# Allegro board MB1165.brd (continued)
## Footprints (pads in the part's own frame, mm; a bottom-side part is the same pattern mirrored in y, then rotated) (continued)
BNX001
  round 1.981 hole 1.219: 1(2.5,2.5) 2(-2.5,2.5) 3(2.5,-2.5) 4(0,0) 5(5,0) 6(-2.5,-2.5)
C310M-6
  rect 5.08x3.048 smd: 1(3.175,0) 2(-3.175,0)
CAE_5R3X5R3_H5R4
  rect 2.718x1.168 smd: 1(-2.05,0) 2(2.05,0)
CLM-120-02-L-D
  rect 0.61x1.499 smd: 1(-9.5,-1.57) 2(-9.5,1.57) 3(-8.5,-1.57) 4(-8.5,1.57) 5(-7.5,-1.57) 6(-7.5,1.57) 7(-6.5,-1.57) 8(-6.5,1.57) 9(-5.5,-1.57) 10(-5.5,1.57) 11(-4.5,-1.57) 12(-4.5,1.57) 13(-3.5,-1.57) 14(-3.5,1.57) 15(-2.5,-1.57) 16(-2.5,1.57) 17(-1.5,-1.57) 18(-1.5,1.57) 19(-0.5,-1.57) 20(-0.5,1.57) 21(0.5,-1.57) 22(0.5,1.57) 23(1.5,-1.57) 24(1.5,1.57) 25(2.5,-1.57) 26(2.5,1.57) 27(3.5,-1.57) 28(3.5,1.57) 29(4.5,-1.57) 30(4.5,1.57) 31(5.5,-1.57) 32(5.5,1.57) 33(6.5,-1.57) 34(6.5,1.57) 35(7.5,-1.57) 36(7.5,1.57) 37(8.5,-1.57) 38(8.5,1.57) 39(9.5,-1.57) 40(9.5,1.57)
  round 4.699 hole 3.2: 41(-15.249,0) 42(15.25,0)
COUPON
  rect 1.422x1.422 hole 1.016: 1(-3.444,-2.54)
  round 1.422 hole 1.016: 2(-3.444,0) 3(-3.444,2.54) 4(3.447,-2.54) 5(3.447,0) 6(3.447,2.54)
DB9_M
  rect 1.778x2.032 hole 0.965: 1(5.537,0)
  oval 1.778x2.032 hole 0.965: 2(2.769,0) 3(0,0) 4(-2.769,0) 5(-5.537,0) 6(4.166,2.794) 7(1.397,2.794) 8(-1.372,2.794) 9(-4.14,2.794)
  oval 4.572x2.286 hole 3.556x1.27: 10(-12.522,1.397) 11(12.522,1.397)
FBGA64_1_11X13
  round 0.457 smd: A1(-3.5,3.5) A2(-2.5,3.5) A3(-1.5,3.5) A4(-0.5,3.5) A5(0.5,3.5) A6(1.5,3.5) A7(2.5,3.5) A8(3.5,3.5) B1(-3.5,2.5) B2(-2.5,2.5) B3(-1.5,2.5) B4(-0.5,2.5) B5(0.5,2.5) B6(1.5,2.5) B7(2.5,2.5) B8(3.5,2.5) C1(-3.5,1.5) C2(-2.5,1.5) C3(-1.5,1.5) C4(-0.5,1.5) C5(0.5,1.5) C6(1.5,1.5) C7(2.5,1.5) C8(3.5,1.5) D1(-3.5,0.5) D2(-2.5,0.5) D3(-1.5,0.5) D4(-0.5,0.5) D5(0.5,0.5) D6(1.5,0.5) D7(2.5,0.5) D8(3.5,0.5) E1(-3.5,-0.5) E2(-2.5,-0.5) E3(-1.5,-0.5) E4(-0.5,-0.5) E5(0.5,-0.5) E6(1.5,-0.5) E7(2.5,-0.5) E8(3.5,-0.5) F1(-3.5,-1.5) F2(-2.5,-1.5) F3(-1.5,-1.5) F4(-0.5,-1.5) F5(0.5,-1.5) F6(1.5,-1.5) F7(2.5,-1.5) F8(3.5,-1.5) G1(-3.5,-2.5) G2(-2.5,-2.5) G3(-1.5,-2.5) G4(-0.5,-2.5) G5(0.5,-2.5) G6(1.5,-2.5) G7(2.5,-2.5) G8(3.5,-2.5) H1(-3.5,-3.5) H2(-2.5,-3.5) H3(-1.5,-3.5) H4(-0.5,-3.5) H5(0.5,-3.5) H6(1.5,-3.5) H7(2.5,-3.5) H8(3.5,-3.5)
FBGA90_0R8_8X13
  round 0.406 smd: A1(-3.2,5.6) A2(-2.4,5.6) A3(-1.6,5.6) A7(1.6,5.6) A8(2.4,5.6) A9(3.2,5.6) B1(-3.2,4.8) B2(-2.4,4.8) B3(-1.6,4.8) B7(1.6,4.8) B8(2.4,4.8) B9(3.2,4.8) C1(-3.2,4) C2(-2.4,4) C3(-1.6,4) C7(1.6,4) C8(2.4,4) C9(3.2,4) D1(-3.2,3.2) D2(-2.4,3.2) D3(-1.6,3.2) D7(1.6,3.2) D8(2.4,3.2) D9(3.2,3.2) E1(-3.2,2.4) E2(-2.4,2.4) E3(-1.6,2.4) E7(1.6,2.4) E8(2.4,2.4) E9(3.2,2.4) F1(-3.2,1.6) F2(-2.4,1.6) F3(-1.6,1.6) F7(1.6,1.6) F8(2.4,1.6) F9(3.2,1.6) G1(-3.2,0.8) G2(-2.4,0.8) G3(-1.6,0.8) G7(1.6,0.8) G8(2.4,0.8) G9(3.2,0.8) H1(-3.2,0) H2(-2.4,0) H3(-1.6,0) H7(1.6,0) H8(2.4,0) H9(3.2,0) J1(-3.2,-0.8) J2(-2.4,-0.8) J3(-1.6,-0.8) J7(1.6,-0.8) J8(2.4,-0.8) J9(3.2,-0.8) K1(-3.2,-1.6) K2(-2.4,-1.6) K3(-1.6,-1.6) K7(1.6,-1.6) K8(2.4,-1.6) K9(3.2,-1.6) L1(-3.2,-2.4) L2(-2.4,-2.4) L3(-1.6,-2.4) L7(1.6,-2.4) L8(2.4,-2.4) L9(3.2,-2.4) M1(-3.2,-3.2) M2(-2.4,-3.2) M3(-1.6,-3.2) M7(1.6,-3.2) M8(2.4,-3.2) M9(3.2,-3.2) N1(-3.2,-4) N2(-2.4,-4) N3(-1.6,-4) N7(1.6,-4) N8(2.4,-4) N9(3.2,-4) P1(-3.2,-4.8) P2(-2.4,-4.8) P3(-1.6,-4.8) P7(1.6,-4.8) P8(2.4,-4.8) P9(3.2,-4.8) R1(-3.2,-5.6) R2(-2.4,-5.6) R3(-1.6,-5.6) R7(1.6,-5.6) R8(2.4,-5.6) R9(3.2,-5.6)
FTR-120-53-L-D-LC
  round 1.194 hole 1.194 unplated: (-11.43,0) (11.43,0)
  rect 0.711x2.896 smd: 1(-12.065,-2.705) 2(-12.065,2.705) 3(-10.795,-2.705) 4(-10.795,2.705) 5(-9.525,-2.705) 6(-9.525,2.705) 7(-8.255,-2.705) 8(-8.255,2.705) 9(-6.985,-2.705) 10(-6.985,2.705) 11(-5.715,-2.705) 12(-5.715,2.705) 13(-4.445,-2.705) 14(-4.445,2.705) 15(-3.175,-2.705) 16(-3.175,2.705) 17(-1.905,-2.705) 18(-1.905,2.705) 19(-0.635,-2.705) 20(-0.635,2.705) 21(0.635,-2.705) 22(0.635,2.705) 23(1.905,-2.705) 24(1.905,2.705) 25(3.175,-2.705) 26(3.175,2.705) 27(4.445,-2.705) 28(4.445,2.705) 29(5.715,-2.705) 30(5.715,2.705) 31(6.985,-2.705) 32(6.985,2.705) 33(8.255,-2.705) 34(8.255,2.705) 35(9.525,-2.705) 36(9.525,2.705) 37(10.795,-2.705) 38(10.795,2.705) 39(12.065,-2.705) 40(12.065,2.705)
FTR-130-53-L-D-LC
  round 1.194 hole 1.194 unplated: (-17.78,0) (17.78,0)
  rect 0.711x2.896 smd: 1(-18.415,-2.705) 2(-18.415,2.705) 3(-17.145,-2.705) 4(-17.145,2.705) 5(-15.875,-2.705) 6(-15.875,2.705) 7(-14.605,-2.705) 8(-14.605,2.705) 9(-13.335,-2.705) 10(-13.335,2.705) 11(-12.065,-2.705) 12(-12.065,2.705) 13(-10.795,-2.705) 14(-10.795,2.705) 15(-9.525,-2.705) 16(-9.525,2.705) 17(-8.255,-2.705) 18(-8.255,2.705) 19(-6.985,-2.705) 20(-6.985,2.705) 21(-5.715,-2.705) 22(-5.715,2.705) 23(-4.445,-2.705) 24(-4.445,2.705) 25(-3.175,-2.705) 26(-3.175,2.705) 27(-1.905,-2.705) 28(-1.905,2.705) 29(-0.635,-2.705) 30(-0.635,2.705) 31(0.635,-2.705) 32(0.635,2.705) 33(1.905,-2.705) 34(1.905,2.705) 35(3.175,-2.705) 36(3.175,2.705) 37(4.445,-2.705) 38(4.445,2.705) 39(5.715,-2.705) 40(5.715,2.705) 41(6.985,-2.705) 42(6.985,2.705) 43(8.255,-2.705) 44(8.255,2.705) 45(9.525,-2.705) 46(9.525,2.705) 47(10.795,-2.705) 48(10.795,2.705) 49(12.065,-2.705) 50(12.065,2.705) 51(13.335,-2.705) 52(13.335,2.705) 53(14.605,-2.705) 54(14.605,2.705) 55(15.875,-2.705) 56(15.875,2.705) 57(17.145,-2.705) 58(17.145,2.705) 59(18.415,-2.705) 60(18.415,2.705)
FTSH-110-01-L-DV
  round 0.965 hole 0.965 unplated: (-5.08,0) (5.08,0)
  rect 0.737x2.794 smd: 1(-5.715,-2.03) 2(-5.715,2.03) 3(-4.445,-2.03) 4(-4.445,2.03) 5(-3.175,-2.03) 6(-3.175,2.03) 7(-1.905,-2.03) 8(-1.905,2.03) 9(-0.635,-2.03) 10(-0.635,2.03) 11(0.635,-2.03) 12(0.635,2.03) 13(1.905,-2.03) 14(1.905,2.03) 15(3.175,-2.03) 16(3.175,2.03) 17(4.445,-2.03) 18(4.445,2.03) 19(5.715,-2.03) 20(5.715,2.03)
FTSH-125-01-F-DV
  round 0.965 hole 0.965 unplated: (-14.605,0) (14.605,0)
  rect 0.737x2.794 smd: 1(-15.24,-2.03) 2(-15.24,2.03) 3(-13.97,-2.03) 4(-13.97,2.03) 5(-12.7,-2.03) 6(-12.7,2.03) 7(-11.43,-2.03) 8(-11.43,2.03) 9(-10.16,-2.03) 10(-10.16,2.03) 11(-8.89,-2.03) 12(-8.89,2.03) 13(-7.62,-2.03) 14(-7.62,2.03) 15(-6.35,-2.03) 16(-6.35,2.03) 17(-5.08,-2.03) 18(-5.08,2.03) 19(-3.81,-2.03) 20(-3.81,2.03) 21(-2.54,-2.03) 22(-2.54,2.03) 23(-1.27,-2.03) 24(-1.27,2.03) 25(0,-2.03) 26(0,2.03) 27(1.27,-2.03) 28(1.27,2.03) 29(2.54,-2.03) 30(2.54,2.03) 31(3.81,-2.03) 32(3.81,2.03) 33(5.08,-2.03) 34(5.08,2.03) 35(6.35,-2.03) 36(6.35,2.03) 37(7.62,-2.03) 38(7.62,2.03) 39(8.89,-2.03) 40(8.89,2.03) 41(10.16,-2.03) 42(10.16,2.03) 43(11.43,-2.03) 44(11.43,2.03) 45(12.7,-2.03) 46(12.7,2.03) 47(13.97,-2.03) 48(13.97,2.03) 49(15.24,-2.03) 50(15.24,2.03)
HDR_2X3-1_2R54-6
  rect 1.524x1.524 hole 1.016: 1(0,0)
  round 1.524 hole 1.016: 2(0,2.54) 3(2.54,0) 4(2.54,2.54) 5(5.08,0)
HDR_2X6_2R54
  rect 1.524x1.524 hole 1.016: 1(0,0)
  round 1.524 hole 1.016: 2(0,2.54) 3(2.54,0) 4(2.54,2.54) 5(5.08,0) 6(5.08,2.54) 7(7.62,0) 8(7.62,2.54) 9(10.16,0) 10(10.16,2.54) 11(12.7,0) 12(12.7,2.54)
HOLE_C9D4R5
  round 8.992 hole 4.496: 1(0,0)
IDC20S
  round 1.524 hole 1.016: 1(0,0) 2(2.54,0) 3(0,-2.54) 4(2.54,-2.54) 5(0,-5.08) 6(2.54,-5.08) 7(0,-7.62) 8(2.54,-7.62) 9(0,-10.16) 10(2.54,-10.16) 11(0,-12.7) 12(2.54,-12.7) 13(0,-15.24) 14(2.54,-15.24) 15(0,-17.78) 16(2.54,-17.78) 17(0,-20.32) 18(2.54,-20.32) 19(0,-22.86) 20(2.54,-22.86)
IDC34S
  rect 1.524x1.524 hole 1.016: 1(0,0)
  round 1.524 hole 1.016: 2(2.54,0) 3(0,-2.54) 4(2.54,-2.54) 5(0,-5.08) 6(2.54,-5.08) 7(0,-7.62) 8(2.54,-7.62) 9(0,-10.16) 10(2.54,-10.16) 11(0,-12.7) 12(2.54,-12.7) 13(0,-15.24) 14(2.54,-15.24) 15(0,-17.78) 16(2.54,-17.78) 17(0,-20.32) 18(2.54,-20.32) 19(0,-22.86) 20(2.54,-22.86) 21(0,-25.4) 22(2.54,-25.4) 23(0,-27.94) 24(2.54,-27.94) 25(0,-30.48) 26(2.54,-30.48) 27(0,-33.02) 28(2.54,-33.02) 29(0,-35.56) 30(2.54,-35.56) 31(0,-38.1) 32(2.54,-38.1) 33(0,-40.64) 34(2.54,-40.64)
IR_VISHAY3
  rect 0.711x1.397 smd: 1(3.325,0) 2(2.375,0) 3(1.425,0) 4(0.475,0) 5(-0.475,0) 6(-1.425,0) 7(-2.375,0) 8(-3.325,0)
LED2_3528
  rect 1.118x1.499 smd: 1(-0.75,-1.5) 2(-0.75,1.5) 3(0.75,1.5) 4(0.75,-1.5)
LQFP48_0R5_9X9
  rect 1.346x0.279 smd: 1(-4.35,2.75) 2(-4.35,2.25) 3(-4.35,1.75) 4(-4.35,1.25) 5(-4.35,0.75) 6(-4.35,0.25) 7(-4.35,-0.25) 8(-4.35,-0.75) 9(-4.35,-1.25) 10(-4.35,-1.75) 11(-4.35,-2.25) 12(-4.35,-2.75) 25(4.35,-2.75) 26(4.35,-2.25) 27(4.35,-1.75) 28(4.35,-1.25) 29(4.35,-0.75) 30(4.35,-0.25) 31(4.35,0.25) 32(4.35,0.75) 33(4.35,1.25) 34(4.35,1.75) 35(4.35,2.25) 36(4.35,2.75)
  rect 0.279x1.346 smd: 13(-2.75,-4.35) 14(-2.25,-4.35) 15(-1.75,-4.35) 16(-1.25,-4.35) 17(-0.75,-4.35) 18(-0.25,-4.35) 19(0.25,-4.35) 20(0.75,-4.35) 21(1.25,-4.35) 22(1.75,-4.35) 23(2.25,-4.35) 24(2.75,-4.35) 37(2.75,4.35) 38(2.25,4.35) 39(1.75,4.35) 40(1.25,4.35) 41(0.75,4.35) 42(0.25,4.35) 43(-0.25,4.35) 44(-0.75,4.35) 45(-1.25,4.35) 46(-1.75,4.35) 47(-2.25,4.35) 48(-2.75,4.35)
MOLEX_47590001
  rect 0.406x1.346 smd: 1(1.3,0) 2(0.65,0) 3(0,0) 4(-0.65,0) 5(-1.3,0)
  oval 1.067x1.6 hole 0.762x0.838: 6(2.275,0.325) 7(-2.275,0.325)
  oval 1.397x1.905 hole 0.838x1.499: 8(-4.15,-2.855) 9(4.15,-2.855)
  rect 2.896x2.007 smd: 10(0,-2.675)
MP34DT01TR
  rect 0.508x1.067 smd: 1(-0.425,0.675) 2(-0.425,-0.675) 3(0.425,-0.675) 4(0.425,0.675)
  round 0.152 smd: 5(-0.025,-1.753)
MSD_PJS008_
  round 0.711 hole 0.711 unplated: (0,0) (7.55,0)
  rect 0.813x1.6 smd: 1(1.475,5.8) 2(2.575,5.8) 3(3.675,5.8) 4(4.775,5.8) 5(5.875,5.8) 6(6.975,5.8) 7(8.075,5.8) 8(9.175,5.8)
  rect 0.838x1.6 smd: 9(10.325,5.8)
  rect 1.956x1.905 smd: 10(11.225,-4.4)
  rect 1.524x3.073 smd: 11(11.45,-7.35)
  rect 1.397x3.429 smd: 12(-3.503,-7.357)
  rect 1.6x3.505 smd: 13(-3.4,3.65)
  rect 1.194x3.099 smd: 14(11.6,4.15)
OSC_4SM_7X5
  rect 1.803x2.007 smd: 1(-2.54,-2.1) 2(2.54,-2.1) 3(2.54,2.1) 4(-2.54,2.1)
PB10
  rect 1.524x1.016 smd: 1(-4.5,-2.223) 2(-4.5,2.223) 3(4.5,2.223) 4(4.5,-2.223)
PJ3028B
  round 2.007 hole 2.007 unplated: (0,0) (7,0)
  rect 1.219x2.489 smd: 2(-3.9,-4) 7(-2,4)
  rect 2.007x2.489 smd: 3(-1,-4) 4(0.8,4) 6(8.2,-4)
  rect 2.489x2.007 smd: 5(12.25,0.8)
PWR_JACK_DC10
  rect 2.032x4.216 hole 1.016x3.2: 1(0,0)
  oval 4.216x2.032 hole 3.2x1.016: 2(-3.1,-5)
  oval 2.032x4.216 hole 1.016x3.2: 3(-6.2,0)
QFN32_0R5_5X5
  oval 0.864x0.279 smd: 1(-2.42,1.75) 2(-2.42,1.25) 3(-2.42,0.75) 4(-2.42,0.25) 5(-2.42,-0.25) 6(-2.42,-0.75) 7(-2.42,-1.25) 8(-2.42,-1.75) 17(2.42,-1.75) 18(2.42,-1.25) 19(2.42,-0.75) 20(2.42,-0.25) 21(2.42,0.25) 22(2.42,0.75) 23(2.42,1.25) 24(2.42,1.75)
  oval 0.279x0.864 smd: 9(-1.75,-2.42) 10(-1.25,-2.42) 11(-0.75,-2.42) 12(-0.25,-2.42) 13(0.25,-2.42) 14(0.75,-2.42) 15(1.25,-2.42) 16(1.75,-2.42) 25(1.75,2.42) 26(1.25,2.42) 27(0.75,2.42) 28(0.25,2.42) 29(-0.25,2.42) 30(-0.75,2.42) 31(-1.25,2.42) 32(-1.75,2.42)
  rect 3.429x3.429 smd: 33(0,0)
QSH-030-01-F-D-A
  round 1.016 hole 1.016 unplated: (-10.065,2.67) (10.065,2.67)
  rect 0.279x2.286 smd: 1(-7.25,-2.87) 2(-7.25,2.87) 3(-6.75,-2.87) 4(-6.75,2.87) 5(-6.25,-2.87) 6(-6.25,2.87) 7(-5.75,-2.87) 8(-5.75,2.87) 9(-5.25,-2.87) 10(-5.25,2.87) 11(-4.75,-2.87) 12(-4.75,2.87) 13(-4.25,-2.87) 14(-4.25,2.87) 15(-3.75,-2.87) 16(-3.75,2.87) 17(-3.25,-2.87) 18(-3.25,2.87) 19(-2.75,-2.87) 20(-2.75,2.87) 21(-2.25,-2.87) 22(-2.25,2.87) 23(-1.75,-2.87) 24(-1.75,2.87) 25(-1.25,-2.87) 26(-1.25,2.87) 27(-0.75,-2.87) 28(-0.75,2.87) 29(-0.25,-2.87) 30(-0.25,2.87) 31(0.25,-2.87) 32(0.25,2.87) 33(0.75,-2.87) 34(0.75,2.87) 35(1.25,-2.87) 36(1.25,2.87) 37(1.75,-2.87) 38(1.75,2.87) 39(2.25,-2.87) 40(2.25,2.87) 41(2.75,-2.87) 42(2.75,2.87) 43(3.25,-2.87) 44(3.25,2.87) 45(3.75,-2.87) 46(3.75,2.87) 47(4.25,-2.87) 48(4.25,2.87) 49(4.75,-2.87) 50(4.75,2.87) 51(5.25,-2.87) 52(5.25,2.87) 53(5.75,-2.87) 54(5.75,2.87) 55(6.25,-2.87) 56(6.25,2.87) 57(6.75,-2.87) 58(6.75,2.87) 59(7.25,-2.87) 60(7.25,2.87)
  rect 2.54x0.635 smd: 61(-8.065,0) 64(8.065,0)
  rect 4.699x0.635 smd: 62(-3.175,0) 63(3.175,0)
RJ45_J0011D01BNL
  round 3.175 hole 3.175 unplated: (-10.16,6.35) (1.27,6.35)
  rect 1.422x1.422 hole 1.016: 1(0,0)
  round 1.422 hole 1.016: 2(-1.27,-2.54) 3(-2.54,0) 4(-3.81,-2.54) 5(-5.08,0) 6(-6.35,-2.54) 7(-7.62,0) 8(-8.89,-2.54) 9(1.88,11.25) 10(-0.66,9.73) 11(-8.23,11.25) 12(-10.77,9.73)
  round 2.388 hole 1.626: 13(-12.32,3.3) 14(3.43,3.3)
SB_0603
  round 0.152 smd: 1(-0.762,0) 2(0.762,0)
SIP2
  round 1.524 hole 1.016: 1(0,0) 2(2.54,0)
SIP3
  rect 1.524x1.524 hole 1.016: 1(0,0)
  round 1.524 hole 1.016: 2(2.54,0) 3(5.08,0)
SMA
  rect 2.007x1.676 smd: 1(-1.9,0) 2(1.9,0)
SOD-323
  rect 0.813x0.813 smd: 1(-1.125,0) 2(1.125,0)
SOIC8_1R27_4R9X6
  rect 0.559x1.778 smd: 1(-1.905,-2.624) 2(-0.635,-2.624) 3(0.635,-2.624) 4(1.905,-2.624) 5(1.905,2.624) 6(0.635,2.624) 7(-0.635,2.624) 8(-1.905,2.624)
SOIC16W_1R27_10R3X10R33
  rect 0.584x1.956 smd: 1(-4.445,-4.795) 2(-3.175,-4.795) 3(-1.905,-4.795) 4(-0.635,-4.795) 5(0.635,-4.795) 6(1.905,-4.795) 7(3.175,-4.795) 8(4.445,-4.795) 9(4.445,4.795) 10(3.175,4.795) 11(1.905,4.795) 12(0.635,4.795) 13(-0.635,4.795) 14(-1.905,4.795) 15(-3.175,4.795) 16(-4.445,4.795)
SOT23-5
  rect 0.635x1.143 smd: 1(-0.95,-1.2) 2(0,-1.2) 3(0.95,-1.2) 4(0.95,1.2) 5(-0.95,1.2)
SOT-23
  rect 0.635x1.143 smd: 1(-0.95,-1.1) 2(0.95,-1.1) 3(0,1.1)
SOT-223
  rect 1.016x1.803 smd: 1(-2.3,-3.15) 2(0,-3.15) 3(2.3,-3.15)
  rect 3.302x1.803 smd: 4(0,3.15)
SOT-353
  rect 0.406x1.194 smd: 1(-0.65,-0.9) 2(0,-0.9) 3(0.65,-0.9) 4(0.65,0.9) 5(-0.65,0.9)
SSM-104-L-DH
  round 1.194 hole 1.194 unplated: (-2.54,0) (2.54,0)
  rect 1.016x2.286 smd: 1(3.81,-4.698) 2(3.81,4.698) 3(1.27,-4.698) 4(1.27,4.698) 5(-1.27,-4.698) 6(-1.27,4.698) 7(-3.81,-4.698) 8(-3.81,4.698)
SSOP28_0R65_10R2X7R8
  rect 0.356x1.753 smd: 1(-4.225,-3.55) 2(-3.575,-3.55) 3(-2.925,-3.55) 4(-2.275,-3.55) 5(-1.625,-3.55) 6(-0.975,-3.55) 7(-0.325,-3.55) 8(0.325,-3.55) 9(0.975,-3.55) 10(1.625,-3.55) 11(2.275,-3.55) 12(2.925,-3.55) 13(3.575,-3.55) 14(4.225,-3.55) 15(4.225,3.55) 16(3.575,3.55) 17(2.925,3.55) 18(2.275,3.55) 19(1.625,3.55) 20(0.975,3.55) 21(0.325,3.55) 22(-0.325,3.55) 23(-0.975,3.55) 24(-1.625,3.55) 25(-2.275,3.55) 26(-2.925,3.55) 27(-3.575,3.55) 28(-4.225,3.55)
SW1_3TH_2R54_10X2R5
  rect 1.422x1.422 hole 1.016: 1(0,0)
  round 1.422 hole 1.016: 2(2.54,0) 3(5.08,0)
SW-JOY
  round 0.711 hole 0.711 unplated: (0,1.9)
  round 0.991 hole 0.991 unplated: (0,-1.9)
  rect 1.016x1.778 smd: 1(-3.608,1.7) 3(-3.608,-1.7) 4(3.608,-1.7) 6(3.608,1.7)
  rect 1.016x1.016 smd: 2(-3.608,0) 5(3.608,0)
  rect 0.813x0.914 smd: 7(0,3.55) 8(0,-3.55)
  rect 0.813x0.61 smd: 9(-1.3,4) 10(1.3,-4)
TAN-A
  rect 1.27x1.524 smd: 1(1.397,0) 2(-1.397,0)
TO263-3
  rect 1.372x3.429 smd: 1(-2.54,-5) 2(0,-5) 3(2.54,-5)
  rect 10.414x10.795 smd: 4(0,3.625)
TP
  round 1.524 hole 1.016: 1(0,0)
TYCO_ZEN056V130A24LS
  rect 0.61x2.21 smd: 1(-1.745,0)
  rect 0.61x0.94 smd: 2(1.745,0.635) 3(1.745,-0.635)
unnamed
  round 3.505 hole 3.505 unplated: (0,0)
USB-B
  rect 1.27x1.27 hole 0.762: 1(0,0)
  round 1.27 hole 0.762: 2(-2.489,0) 3(-2.489,-2.032) 4(0,-2.032)
  round 3.175 hole 2.413: 5(-7.391,-4.699) 6(4.801,-4.699)
XTAL1
  round 1.27 hole 0.762: 1(0,0) 2(-5.08,0)
XTAL_2SM_3R2X1R5
  rect 1.295x1.6 smd: 1(-1.15,0) 2(1.15,0)
XTAL_2SM_12R7X4R7
  rect 5.486x1.499 smd: 1(-4.25,0) 2(4.25,0)
XTAL_SOCKET
  round 2.108 hole 1.346: 1(0,0) 2(-5.08,0)

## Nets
+1V8: C67.1 C71.1 C73.1 C90.1 C105.1 C106.2 CN4.1 CN4.2 R26.2 R220.2 R225.2 TP1.1 U20.2 U20.4 U23.D1 U23.D8 U23.G9 X3.4
+2V8: C19.1 C122.1 C123.1 CN4.39 CN4.40 R16.1 R219.2 R224.2 T5.1 T6.1 TP5.1 U2.2 U2.4
+3V3: B2.1 B2.4 C1.1 C3.1 C26.1 C28.1 C29.1 C34.2 C38.2 C46.2 C47.2 C52.1 C61.1 C62.1 C72.1 C87.1 C88.1 C89.1 C94.1 C107.1 C110.1 C130.1 C138.1 C148.1 C149.1 C150.1 C151.1 C152.1 C153.1 C154.1 C157.1 C158.1 C159.1 C160.1 C161.1 C162.1 C163.1 C164.1 C165.1 C166.1 C167.1 C168.1 C169.1 C170.1 C171.1 C172.1 C174.2 C176.1 C177.2 C179.2 C182.2 C183.1 CN1.28 CN2.5 CN5.48 CN6.48 CN9.4 CN9.5 CN11.40 CN12.1 CN15.36 CN16.1 CN16.2 CN17.4 CN18.50 JP2.1 JP10.1 JP16.3 L6.1 LD1.1 LD2.1 LD3.1 LD4.1 R1.1 R2.1 R14.2 R21.2 R68.1 R69.2 R70.2 R71.2 R72.2 R73.2 R75.2 R76.2 R79.1 R83.1 R84.2 R86.2 R89.2 R90.1 R105.1 R106.2 R108.2 R110.1 R112.1 R115.1 R118.2 R120.2 R121.1 R122.2 R123.2 R124.2 R125.2 R129.2 R131.2 R132.2 R134.2 R143.2 R145.1 R146.1 R148.1 R149.1 R150.1 R151.1 R152.1 R154.1 R159.2 R165.2 R169.1 R171.2 R174.1 R178.1 R181.2 R197.1 R198.1 R199.1 R200.1 R201.1 R204.2 R207.1 R215.1 R218.1 R279.2 R282.2 RV1.1 SW1.1 SW2.1 T1.2 TP4.1 U1.7 U3.2 U5.22 U5.26 U6.22 U6.32 U6.48 U8.6 U8.16 U8.25 U8.30 U8.31 U9.D8 U9.F1 U9.G5 U15.A7 U15.B2 U15.B7 U15.C9 U15.D9 U15.E1 U15.F9 U15.L1 U15.L7 U15.M9 U15.N9 U15.P2 U15.P7 U15.R7 U16.A6 U16.D6 U16.E1 U19.2 U19.4 U20.3 U22.1 U22.24 U22.36 U22.48 U23.B2 U23.C2 U23.D2 U23.E9 U24.3
+3V3_ST_LINK: C55.2 C57.1 C173.2 C175.2 C178.2 C180.2 CN20.4 JP20.1 R190.2 R286.1 R291.2 T4.3 U17.5 U21.1 U21.9 U21.24 U21.36 U21.48
+5V: C58.1 CN1.25 CN5.60 CN6.60 D15.1 JP14.2 JP14.4 JP14.6 JP14.8 JP14.10 JP14.12 L4.1 L8.1 R130.2 TP14.1 U2.3 U7.5 U11.5 U19.3
D5V: CN5.49 CN6.49 D7.1 JP14.7
GND: B1.1 B1.4 B3.1 B3.4 B4.5 B4.7 B4.8 B4.9 B4.10 BT1.2 C1.2 C2.2 C3.2 C4.2 C5.2 C6.1 C7.1 C8.1 C9.1 C10.1 C11.2 C12.1 C13.1 C14.1 C15.2 C16.1 C17.2 C18.1 C19.2 C20.2 C21.2 C22.2 C23.2 C24.1 C27.1 C29.2 C30.2 C31.2 C32.2 C33.1 C34.1 C35.2 C36.2 C37.2 C38.1 C39.2 C40.2 C41.2 C42.2 C43.2 C44.2 C45.2 C46.1 C47.1 C48.2 C49.2 C52.2 C53.1 C54.1 C55.1 C56.1 C57.2 C58.2 C59.1 C60.2 C61.2 C62.2 C65.2 C67.2 C68.1 C70.2 C71.2 C72.2 C73.2 C74.2 C76.1 C77.2 C78.1 C79.2 C82.1 C83.1 C84.2 C85.2 C86.2 C87.2 C88.2 C89.2 C90.2 C91.2 C93.2 C94.2 C95.1 C96.1 C97.1 C98.1 C99.1 C102.1 C104.2 C105.2 C106.1 C108.2 C109.2 C110.2 C111.2 C112.2 C113.1 C114.2 C115.2 C116.1 C117.2 C118.2 C119.2 C120.2 C121.2 C122.2 C123.2 C124.2 C125.2 C126.2 C127.2 C128.2 C129.2 C131.2 C132.2 C133.2 C134.2 C135.2 C136.2 C137.1 C138.2 C140.2 C141.2 C142.1 C143.2 C144.2 C145.2 C146.1 C147.2 C148.2 C149.2 C150.2 C151.2 C152.2 C153.2 C154.2 C157.2 C158.2 C159.2 C160.2 C161.2 C162.2 C163.2 C164.2 C165.2 C166.2 C167.2 C168.2 C169.2 C170.2 C171.2 C172.2 C173.1 C174.1 C175.1 C176.2 C177.1 C178.1 C179.1 C180.1 C181.1 C182.1 C183.2 CN1.2 CN1.4 CN1.6 CN1.8 CN1.10 CN1.12 CN1.16 CN1.18 CN1.20 CN1.22 CN1.24 CN1.30 CN1.32 CN2.7 CN3.2 CN4.3 CN4.4 CN4.7 CN4.8 CN4.11 CN4.12 CN4.16 CN4.21 CN4.22 CN4.37 CN4.38 CN4.41 CN4.42 CN5.1 CN5.10 CN5.19 CN5.30 CN5.39 CN5.50 CN5.59 CN6.1 CN6.10 CN6.19 CN6.30 CN6.39 CN6.50 CN6.59 CN7.5 CN7.10 CN7.11 CN9.8 CN9.13 CN9.14 CN10.9 CN10.10 CN10.29 CN10.30 CN11.9 CN11.10 CN11.29 CN11.30 CN12.3 CN12.5 CN12.9 CN12.11 CN12.13 CN12.15 CN12.17 CN12.19 CN13.5 CN13.6 CN13.7 CN13.8 CN13.9 CN13.10 CN14.5 CN14.6 CN14.7 CN14.8 CN14.9 CN14.10 CN15.1 CN15.7 CN15.13 CN15.19 CN15.61 CN15.62 CN15.63 CN15.64 CN16.4 CN16.6 CN16.8 CN16.10 CN16.12 CN16.14 CN16.16 CN16.18 CN16.20 CN17.6 CN17.9 CN18.1 CN18.2 CN18.19 CN18.20 CN18.30 CN18.34 CN18.37 CN20.2 CN21.2 CN22.4 CN22.5 CN22.6 CN23.3 CN23.6 CN23.10 CN23.11 CN25.2 CN27.3 CN28.2 CN28.5 D3.B1 D3.B2 D4.B1 D4.B2 D5.D2 D6.D2 D14.3 H1.1 H2.1 H3.1 H4.1 JP11.1 JP12.1 JP21.1 L1.1 L3.1 L5.4 L5.5 L5.6 L9.1 LD10.2 LD12.1 R7.2 R13.2 R22.2 R24.1 R39.1 R74.1 R77.1 R88.1 R91.1 R97.1 R101.1 R116.1 R127.1 R128.1 R133.1 R136.1 R137.1 R141.1 R156.2 R157.1 R158.2 R161.2 R162.2 R164.1 R167.1 R168.1 R170.1 R173.2 R176.1 R184.2 R195.2 R202.1 R206.2 R208.1 R210.2 R211.2 R212.1 R229.1 R231.1 R234.1 R239.1 R289.1 R294.1 RV1.3 SB84.1 SW1.3 SW2.3 T2.2 T7.2 T8.2 TP2.1 TP3.1 TP13.1 TP16.1 U1.5 U1.8 U3.10 U4.F2 U4.F6 U4.F7 U4.F8 U4.F9 U4.F10 U4.G6 U4.G10 U4.G12 U4.H6 U4.H10 U4.J6 U4.J10 U4.K6 U4.K7 U4.K8 U4.K9 U4.K10 U4.L6 U4.M1 U4.N1 U5.23 U5.25 U6.15 U6.19 U6.35 U6.36 U6.47 U7.2 U8.1 U8.2 U8.33 U9.E8 U9.H2 U9.H7 U10.2 U11.2 U13.2 U14.2 U15.A3 U15.B3 U15.B8 U15.C1 U15.D1 U15.E9 U15.F1 U15.L3 U15.L9 U15.M1 U15.N1 U15.P3 U15.P8 U15.R3 U16.D1 U16.E6 U17.2 U18.4 U19.1 U20.1 U21.8 U21.23 U21.35 U21.47 U22.8 U22.23 U22.35 U22.47 U23.A1 U23.A3 U23.A4 U23.A5 U23.C1 U23.D6 U23.E2 U23.E7 U23.E8 U23.F7 U23.G5 U23.H9 U24.2 U25.5 U26.2 U26.5 X3.2
VBUS_FS1: C49.1 CN6.54 CN13.1 D5.B3 D9.1 JP14.3 R100.1 R253.2 U11.1
VBUS_FS2: CN14.1 D6.B3 D10.1 JP14.5 R126.1 R255.1 SB14.1
VBUS_HS: CN8.1 D3.A1 D8.1 JP14.1 L2.2
VDD_MCU: C26.2 C28.2 C107.2 C109.1 C111.1 C112.1 C115.1 C117.1 C118.1 C119.1 C120.1 C121.1 C124.1 C125.1 C126.1 C127.1 C128.1 C129.1 C130.2 C131.1 C132.1 C133.1 C134.1 C135.1 C136.1 JP2.2 L7.1 U4.E7 U4.E8 U4.E9 U4.E10 U4.F4 U4.F5 U4.F11 U4.G5 U4.G11 U4.H5 U4.H11 U4.J5 U4.J11 U4.K5 U4.K11 U4.L7 U4.L8 U4.L9 U4.L10
VDDA: C114.1 C116.2 L7.2 R33.1 TP9.1 U4.R1
A0: CN11.14 R236.2 U9.E2 U15.G8 U16.A3
A1: CN11.12 R232.2 U9.D2 U15.G9 U16.A4
A2: CN11.8 R230.2 U9.C2 U15.F7 U16.A5
A3: CN11.5 R226.2 U9.A2 U15.F3 U16.B3
A4: CN11.3 R223.2 U9.B2 U15.G1 U16.B4
A5: CN11.1 R221.2 U9.D3 U15.G2 U16.C3
A6: CN10.5 R248.2 U9.C3 U15.G3 U16.C4
A7: CN10.3 R245.2 U9.A3 U15.H1 U16.D4
A8: CN10.4 R249.2 U9.B6 U15.H2 U16.H2
A9: CN10.18 R261.2 U9.A6 U15.J3 U16.H3
A10: CN10.6 R251.2 U9.C6 U15.G7 U16.H4
A11: CN10.7 R250.2 U9.D6 U15.H9 U16.H5
A12: CN10.33 R269.2 U9.B7 U16.G3
A13: CN10.34 R257.2 U9.A7 U16.G4
A14: CN10.28 R270.2 U9.C7 U15.J7 U16.F3
A15: CN10.25 R259.2 U9.D7 U15.H8 U16.F4
A16: CN10.21 R260.1 U9.E7 U16.E4
A17: CN10.23 R271.2 U9.B3 U16.D3
A18: CN10.31 R258.2 U9.C4 U16.H1
A19: CN11.13 R37.2 R234.2 U9.D5 U16.G2
A20: CN11.11 R35.2 R231.2 U9.D4 U16.H6
A21: CN11.4 R24.2 R32.2 U9.C5
A22: CN11.7 R34.2 R229.2 U9.B8
A23: CN11.16 R38.2 R39.2 U9.C8
AIN_1: R169.2 R170.2 U21.10
BOOT0: JP1.2 R3.1 U4.E6
CAMERA_CLK: CN4.20 X3.3
D0: CN10.39 R268.2 U9.E3 U15.R8 U16.B6
D1: CN10.38 R256.2 U9.H3 U15.N7 U16.C5
D2: CN11.31 R262.2 U9.E4 U15.R9 U16.C6
D3: CN11.32 R273.2 U9.H4 U15.N8 U16.D5
D4: CN10.11 R58.2 U9.H5 U15.P9 U16.E5
D5: CN10.14 R50.2 U9.E5 U15.M8 U16.F5
D6: CN10.12 R49.2 U9.H6 U15.M7 U16.F6
D7: CN10.13 R59.2 U9.E6 U15.L8 U16.G6
D8: CN10.16 R51.2 U9.F3 U15.L2 U16.B1
D9: CN10.15 R60.2 U9.G3 U15.M3 U16.C1
D10: CN10.19 R62.2 U9.F4 U15.M2 U16.C2
D11: CN10.20 R52.2 U9.G4 U15.P1 U16.D2
D12: CN10.17 R61.2 U9.F5 U15.N2 U16.E2
D13: CN10.35 R56.2 U9.G6 U15.R1 U16.F2
D14: CN10.37 R65.2 U9.F6 U15.N3 U16.F1
D15: CN10.36 R66.2 U9.G7 U15.R2 U16.G1
D16: CN10.22 R53.1 U15.E8
D17: CN10.26 R54.1 U15.D7
D18: CN10.24 R63.1 U15.D8
D19: CN10.27 R64.1 U15.B9
D20: CN10.32 R55.1 U15.C8
D21: CN11.39 R266.1 U15.A9
D22: CN11.38 R276.1 U15.C7
D23: CN11.36 R275.1 U15.A8
D24: CN11.37 R265.1 U15.A2
D25: CN11.35 R264.1 U15.C3
D26: CN11.33 R263.1 U15.A1
D27: CN11.34 R274.1 U15.C2
D28: CN11.22 R247.1 U15.B1
D29: CN11.18 R240.1 U15.D2
D30: CN11.20 R241.1 U15.D3
D31: CN11.21 R244.1 U15.E2
DSI_VDD12: C31.1 C140.1 C141.1 U4.G13 U4.K12
E5V: C60.1 D12.1 JP14.9 L5.3
I2C1_SCL_C: CN4.13 R219.1 R295.2 T5.2
I2C1_SDA_C: CN4.14 R224.1 R296.2 T6.2
LCD_B0: CN6.27 CN18.21 U4.B10
LCD_B1: CN6.15 CN18.23 U4.C7
LCD_B2: CN6.20 CN18.25 U4.C9
LCD_B3: CN6.22 CN18.27 U4.D10
LCD_B4: CN6.16 CN18.29 R194.1 U4.D8
LCD_B5: CN6.13 CN18.31 R193.1 U4.D7
LCD_B6: CN6.12 CN18.33 R192.1 U4.C6
LCD_B7: CN6.11 CN18.35 R191.1 U4.C5
LCD_BL_CTRL: CN15.53 CN18.43 SB80.1
LCD_G0: CN18.4 SB51.1
LCD_G1: CN18.6 SB76.1
LCD_G2: CN6.5 CN18.8 U4.G4
LCD_G3: CN6.17 CN18.10 U4.C8
LCD_G4: CN6.26 CN18.12 U4.B9
LCD_G5: CN18.14 SB57.2
LCD_G6: CN18.16 SB30.2
LCD_G7: CN18.18 SB28.1
LCD_R0: CN18.3 SB8.2
LCD_R1: CN5.54 CN18.5 U4.R6
LCD_R2: CN5.58 CN18.7 U4.R7
LCD_R3: CN5.56 CN15.49 CN18.9 U4.P7
LCD_R4: CN5.31 CN18.11 U4.N8
LCD_R5: CN5.34 CN18.13 U4.M9
LCD_R6: CN5.42 CN18.15 U4.M14
LCD_R7: CN5.51 CN18.17 U4.J15
LED_STLINK: R188.1 R189.1 U21.30
LOOP: TP15.1 U22.14
MCO: U21.29
MFX_SWCLK: CN21.3 U22.37
MFX_SWDIO: CN21.1 U22.34
MIC_CLK: CN25.3 CN28.3 JP18.2 SB25.1
MIC_DATA: CN25.1 CN28.1 JP17.2 SB26.2
MIC_VDD: C93.1 C104.1 CN25.4 CN28.4 JP16.2 R185.2 R186.2 U25.1 U26.1
MII_TXD0: R36.2 SB27.1 U6.3
NETB2_2: B2.2 B2.3 C103.2 R205.1 R206.1
NETB3_2: B3.2 B3.3 C100.2 R203.1 R204.1
NETB4_1: B4.1 C97.2 R199.2 U22.20
NETB4_2: B4.2 C96.2 R198.2 U22.18
NETB4_3: B4.3 C95.2 R197.2 U22.19
NETB4_4: B4.4 C99.2 R201.2 U22.39
NETB4_6: B4.6 C98.2 R200.2 U22.40
NETBT1_1: BT1.1 JP10.3
NETC2_1: C2.1 C4.1 R1.2 U1.6
NETC5_1: C5.1 R7.1 R16.2 U2.1
NETC6_2: C6.2 CN1.31 SB2.2 SB46.1
NETC7_2: C7.2 CN1.27 SB1.2 SB66.1
NETC8_2: C8.2 CN1.33 SB33.1
NETC9_2: C9.2 CN1.34 SB42.1
NETC10_2: C10.2 CN1.29 SB68.1
NETC11_1: C11.1 R8.2 SB69.2
NETC12_2: C12.2 R9.1 SB59.2
NETC13_2: C13.2 R10.1 SB49.2
NETC14_2: C14.2 R11.1 SB41.2
NETC15_1: C15.1 R12.2 R13.1 SB52.2
NETC16_2: C16.2 CN1.1 R14.1 R15.1
NETC17_1: C17.1 SB2.1
NETC18_2: C18.2 SB1.1 SB75.1
NETC20_1: C20.1 R20.2 X1.2
NETC21_1: C21.1 R18.1 X2.1
NETC22_1: C22.1 R19.1 X2.2
NETC24_2: C24.2 R30.1 R31.1
NETC25_1: C25.1 U5.1
NETC25_2: C25.2 U5.2
NETC27_2: C27.2 U5.3
NETC30_1: C30.1 JP7.1 X4.1
NETC32_1: C32.1 U4.E11
NETC33_2: C33.2 R67.2 X4.2
NETC35_1: C35.1 C36.1 C44.1 C45.1 CN8.5 CN8.6 CN8.7 CN8.8 CN8.9 CN8.10 L1.2
NETC37_1: C37.1 SB13.1 SB14.2 U7.1
NETC39_1: C39.1 R81.2 U8.28 X5.1
NETC40_1: C40.1 R81.1 U8.27 X5.2
NETC41_1: C41.1 R79.2 U9.B5
NETC42_1: C42.1 C147.1 U8.29
NETC43_1: C43.1 C48.1 U8.15 U8.26
NETC53_2: C53.2 U17.4
NETC54_2: C54.2 C56.2 D7.2 D8.2 D9.2 D10.2 D11.2 D12.2 U17.1 U17.3
NETC63_1: C63.1 C66.1 CN18.45 L4.2
NETC63_2: C63.2 C66.2 CN18.47 CN18.49 L3.2
NETC64_1: C64.1 D13.3 L5.1 Z1.2
NETC64_2: C64.2 CN19.2 CN19.3 D13.2 L5.2 Z1.1
NETC68_2: C68.2 U23.C9
NETC69_1: C69.1 U23.D7
NETC69_2: C69.2 CN27.2 R160.1 R212.2
NETC70_1: C70.1 U23.D9
NETC74_1: C74.1 U23.E6
NETC75_1: C75.1 U23.H8
NETC75_2: C75.2 U23.G8
NETC76_2: C76.2 JP16.1 U23.A7
NETC77_1: C77.1 U23.G7
NETC78_2: C78.2 R160.2 U23.B6
NETC79_1: C79.1 U23.H7
NETC80_1: C80.1 CN27.4 U23.G6
NETC80_2: C80.2 R161.1
NETC81_1: C81.1 CN27.6 U23.H6
NETC81_2: C81.2 R162.1
NETC82_2: C82.2 C86.1 L6.2 U22.9
NETC83_2: C83.2 D16.1 R165.1 U22.7
NETC91_1: C91.1 U23.F1
NETC92_1: C92.1 R183.1 R184.1
NETC92_2: C92.2 U23.A2
NETC100_1: C100.1 R202.2
NETC101_1: C101.1 R208.2 R209.2
NETC101_2: C101.2 U23.B3
NETC103_1: C103.1 R207.2
NETC137_2: C137.2 U5.27
NETC139_1: C139.1 U5.24
NETC139_2: C139.2 U5.28
NETC142_2: C142.2 C144.1 C145.1 C146.2 U6.18 U6.23 U6.37
NETC143_1: C143.1 U4.L11
NETC155_1: C155.1 C156.1 CN15.21 CN15.23 L8.2
NETC155_2: C155.2 C156.2 CN15.27 CN15.29 L9.2
NETCN1_3: CN1.3 SB82.2
NETCN1_5: CN1.5 SB43.1
NETCN1_9: CN1.9 SB64.1
NETCN1_11: CN1.11 SB78.2
NETCN1_13: CN1.13 SB61.1
NETCN1_14: CN1.14 R12.1
NETCN1_15: CN1.15 R11.2
NETCN1_17: CN1.17 R10.2
NETCN1_19: CN1.19 R9.2
NETCN1_21: CN1.21 SB60.2
NETCN1_23: CN1.23 SB58.2
NETCN1_26: CN1.26 R8.1
NETCN2_1: CN2.1 R4.2
NETCN2_3: CN2.3 R5.2
NETCN2_4: CN2.4 R17.1
NETCN3_1: CN3.1 R29.1 R30.2
NETCN4_15: CN4.15 R218.2 U22.33
NETCN4_17: CN4.17 R220.1 U22.32
NETCN4_18: CN4.18 TP7.1
NETCN4_19: CN4.19 R225.1 U22.31
NETCN4_31: CN4.31 SB47.1
NETCN4_34: CN4.34 TP8.1
NETCN4_35: CN4.35 TP11.1
NETCN4_36: CN4.36 TP10.1
NETCN5_3: CN5.3 SB37.2
NETCN5_5: CN5.5 R213.2
NETCN5_6: CN5.6 SB38.2
NETCN6_3: CN6.3 SB36.2
NETCN6_4: CN6.4 SB35.2
NETCN7_2: CN7.2 U5.6
NETCN7_3: CN7.3 U5.10
NETCN7_6: CN7.6 U5.5
NETCN7_8: CN7.8 U5.7
NETCN8_2: CN8.2 D4.A1 U8.8
NETCN8_3: CN8.3 D4.A2 U8.7
NETCN8_4: CN8.4 D3.A2 U8.5
NETCN9_1: CN9.1 R110.2 U6.17
NETCN9_2: CN9.2 R105.2 U6.16
NETCN9_3: CN9.3 R83.2 U6.14
NETCN9_6: CN9.6 R90.2 U6.13
NETCN9_9: CN9.9 R118.1
NETCN9_10: CN9.10 R70.1 U6.28
NETCN9_11: CN9.11 R73.1 U6.26
NETCN9_12: CN9.12 R72.1
NETCN11_6: CN11.6 JP6.1 R86.1 U9.A4
NETCN12_2: CN12.2 CN16.7 R80.1 R129.1 U14.1
NETCN12_4: CN12.4 CN16.9 R87.1 R128.2 U14.3
NETCN12_6: CN12.6 CN16.13 R92.1 R102.2 R131.1 U14.4
NETCN12_8: CN12.8 CN16.5 R93.1 R123.1 U13.5
NETCN12_10: CN12.10 CN16.15 R96.1 U14.5
NETCN12_12: CN12.12 SB11.1 U13.1
NETCN12_14: CN12.14 R102.1 SB10.1 U10.5
NETCN12_16: CN12.16 R104.1 SB6.1 U10.4
NETCN12_18: CN12.18 SB3.1 U10.3
NETCN12_20: CN12.20 SB18.1 U10.1
NETCN13_2: CN13.2 D5.D1 R281.1
NETCN13_3: CN13.3 D5.C1 R280.1
NETCN13_4: CN13.4 D5.A3 R107.1
NETCN14_2: CN14.2 D6.D1 R284.1
NETCN14_3: CN14.3 D6.C1 R283.1
NETCN14_4: CN14.4 D6.A3 SB70.1
NETCN15_3: CN15.3 U4.H12
NETCN15_5: CN15.5 U4.H13
NETCN15_9: CN15.9 U4.J12
NETCN15_11: CN15.11 U4.J13
NETCN15_15: CN15.15 U4.F12
NETCN15_17: CN15.17 U4.F13
NETCN16_3: CN16.3 R103.1 R104.2 R124.1 U13.4
NETCN16_11: CN16.11 R132.1 R133.2
NETCN16_17: CN16.17 R136.2
NETCN16_19: CN16.19 R137.2
NETCN17_1: CN17.1 R150.2 R278.1
NETCN17_2: CN17.2 R149.2 R272.1
NETCN17_3: CN17.3 R148.2 SB83.1
NETCN17_7: CN17.7 R146.2 SB81.2
NETCN17_8: CN17.8 R145.2 R252.1
NETCN17_10: CN17.10 R142.2
NETCN18_22: CN18.22 R153.1
NETCN19_1: CN19.1 D13.1
NETCN21_4: CN21.4 R154.2
NETCN22_2: CN22.2 R177.1
NETCN22_3: CN22.3 R180.1 R182.1
NETCN23_2: CN23.2 D14.1 JP13.2 U24.6
NETCN23_5: CN23.5 R176.2
NETCN23_7: CN23.7 D14.2 R175.1 U24.7
NETCN23_9: CN23.9 R174.2
NETCN25_5: CN25.5 R185.1
NETCN26_2: CN26.2 R211.1
NETCN26_3: CN26.3 R210.1
NETCN26_4: CN26.4 R209.1
NETCN26_6: CN26.6 R183.2
NETD1_1: D1.1 U5.20
NETD1_2: D1.2 JP1.1
NETD2_2: D2.2 JP4.1
NETD5_C3: D5.C3 R280.2 SB71.1
NETD6_C3: D6.C3 R283.2 SB62.1
NETD6_D3: D6.D3 R284.2 SB65.1
NETD15_2: D15.2 R196.1
NETJP3_2: JP3.2 R31.2
NETJP4_2: JP4.2 U5.16
NETJP6_3: JP6.3 JP17.3
NETJP7_2: JP7.2 U6.34
NETJP7_3: JP7.3 SB77.1
NETJP8_1: JP8.1 U5.17
NETJP8_2: JP8.2 JP15.1
NETJP8_3: JP8.3 U1.4
NETJP9_2: JP9.2 U24.4
NETJP10_2: JP10.2 U4.C1
NETJP11_2: JP11.2 R106.1 U9.B4
NETJP12_2: JP12.2 R173.1 U24.8
NETJP12_3: JP12.3 R181.1
NETJP13_1: JP13.1 R175.2
NETJP17_1: JP17.1 U23.A9
NETJP18_1: JP18.1 U23.C6
NETJP18_3: JP18.3 R277.2
NETJP19_1: JP19.1 U1.3 U5.13
NETJP19_2: JP19.2 SB72.1
NETJP20_2: JP20.2 R195.1 R196.2 U21.39
NETJP21_2: JP21.2 R286.2 U21.21
NETL2_1: L2.1 R78.2 R95.2 SB13.2
NETLD1_2: LD1.2 R194.2
NETLD2_2: LD2.2 R193.2
NETLD3_2: LD3.2 R192.2
NETLD4_2: LD4.2 R191.2
NETLD5_1: LD5.1 R89.1
NETLD5_2: LD5.2 T7.3
NETLD6_1: LD6.1 R279.1
NETLD6_2: LD6.2 R111.2 R112.2 U7.3 U8.10
NETLD7_1: LD7.1 R108.1
NETLD7_2: LD7.2 T8.3
NETLD8_1: LD8.1 R120.1
NETLD8_2: LD8.2 R119.2 R121.2 U11.3
NETLD9_1: LD9.1 R122.1
NETLD9_2: LD9.2 T2.3
NETLD10_1: LD10.1 R130.1
NETLD11_1: LD11.1 R187.2
NETLD11_2: LD11.2 R144.2 U18.8
NETLD12_2: LD12.2 R188.2
NETLD12_3: LD12.3 R189.2
NETLD12_4: LD12.4 R190.1
NETR2_2: R2.2 U1.1
NETR3_2: R3.2 SW1.2
NETR6_1: R6.1 SW2.2
NETR21_1: R21.1 R22.1 U4.E5
NETR23_1: R23.1 U4.K1
NETR25_1: R25.1 U4.K2
NETR26_1: R26.1 X3.1
NETR27_1: R27.1 U4.L2
NETR28_1: R28.1 R29.2
NETR28_2: R28.2 RV1.2
NETR32_1: R32.1 SB3.2 SB4.2 SB5.2 U4.B1
NETR34_1: R34.1 SB17.2 SB18.2 SB19.2 U4.B2
NETR35_1: R35.1 SB6.2 SB7.2 U4.A1
NETR37_1: R37.1 SB9.2 SB10.2 U4.A2
NETR38_1: R38.1 R238.2 SB11.2 U4.A3
NETR40_1: R40.1 U4.B6
NETR41_1: R41.1 U4.B7
NETR42_1: R42.1 U6.46
NETR43_1: R43.1 U6.45
NETR43_2: R43.2 SB55.2
NETR44_1: R44.1 U6.44
NETR44_2: R44.2 SB73.2
NETR45_1: R45.1 U6.43
NETR45_2: R45.2 SB53.2
NETR46_1: R46.1 U6.39
NETR46_2: R46.2 SB45.1
NETR47_1: R47.1 U6.38
NETR47_2: R47.2 SB39.1
NETR48_1: R48.1 U4.P8
NETR49_1: R49.1 U4.P9
NETR50_1: R50.1 U4.N9
NETR51_1: R51.1 U4.P10
NETR52_1: R52.1 U4.P11
NETR53_2: R53.2 U4.P14
NETR54_2: R54.2 U4.N14
NETR55_2: R55.2 U4.M15
NETR56_1: R56.1 U4.L15
NETR57_1: R57.1 U6.1
NETR57_2: R57.2 SB54.2
NETR58_1: R58.1 U4.R8
NETR59_1: R59.1 U4.R9
NETR60_1: R60.1 U4.R10
NETR61_1: R61.1 U4.R11
NETR62_1: R62.1 U4.R12
NETR63_2: R63.2 U4.P15
NETR64_2: R64.2 U4.N15
NETR65_1: R65.1 U4.L14
NETR66_1: R66.1 U4.K15
NETR67_1: R67.1 U6.33
NETR68_2: R68.2 U6.7 U22.26
NETR69_1: R69.1 SB40.1 U6.30
NETR71_1: R71.1 U6.27
NETR74_2: R74.2 R78.1 T7.1
NETR75_1: R75.1 U6.20
NETR76_1: R76.1 U6.21
NETR77_2: R77.2 U6.24
NETR82_1: R82.1 U8.24
NETR84_1: R84.1 R85.1 U9.F2
NETR88_2: R88.2 SB15.2 SB16.2 U7.4
NETR91_2: R91.2 U8.32
NETR94_1: R94.1 U8.21
NETR95_1: R95.1 U8.4
NETR97_2: R97.2 R100.2 T8.1
NETR98_1: R98.1 U8.20
NETR99_1: R99.1 U9.A5 U16.G5
NETR101_2: R101.2 T1.3 U8.9
NETR109_1: R109.1 U8.18
NETR111_1: R111.1 U22.29
NETR113_1: R113.1 U8.14
NETR114_1: R114.1 R115.2 T1.1
NETR116_2: R116.2 R117.1 U11.4
NETR117_2: R117.2 U22.17
NETR119_1: R119.1 U22.16
NETR126_2: R126.2 R127.2 T2.1
NETR134_1: R134.1 R135.1 U16.B5
NETR140_1: R140.1 R141.2
NETR140_2: R140.2 U18.5
NETR142_1: R142.1 R143.1 U22.28
NETR155_1: R155.1 U22.21
NETR155_2: R155.2 U22.22
NETR156_1: R156.1 U22.44
NETR157_2: R157.2 U21.44
NETR158_1: R158.1 R159.1 U22.45
NETR163_1: R163.1 R164.2 U22.2
NETR163_2: R163.2 R205.2 SB44.1
NETR167_2: R167.2 U21.2
NETR168_2: R168.2 U21.3
NETR171_1: R171.1 U23.D4 U23.D5
NETR172_2: R172.2 U23.F3
NETR178_2: R178.2 U23.G2
NETR179_2: R179.2 U23.H1
NETR182_2: R182.2 T4.2
NETR186_1: R186.1 U25.2
NETR214_2: R214.2 U4.H3
NETR216_1: R216.1 U3.8
NETR217_2: R217.2 U3.9
NETR221_1: R221.1 U4.K3
NETR222_1: R222.1 U4.L1
NETR223_1: R223.1 U4.J2
NETR226_1: R226.1 U4.H2
NETR227_1: R227.1 U3.1
NETR228_2: R228.2 U3.15
NETR230_1: R230.1 U4.G2
NETR232_1: R232.1 U4.E2
NETR233_2: R233.2 U6.5
NETR235_2: R235.2 U6.4
NETR236_1: R236.1 U4.D2
NETR237_1: R237.1 U4.L3
NETR238_1: R238.1 U6.6
NETR239_2: R239.2 U4.L5
NETR240_2: R240.2 U4.D4
NETR241_2: R241.2 U4.E4
NETR242_2: R242.2 U6.2
NETR243_2: R243.2 SB63.1 U4.J4
NETR244_2: R244.2 SB12.1 U4.D5
NETR245_1: R245.1 U4.N6
NETR246_2: R246.2 U4.J3
NETR247_2: R247.2 U4.D6
NETR248_1: R248.1 U4.M6
NETR249_1: R249.1 U4.P6
NETR250_1: R250.1 U4.M7
NETR251_1: R251.1 U4.N7
NETR254_1: R254.1 SB27.2
NETR256_1: R256.1 U4.K13
NETR257_1: R257.1 U4.M12
NETR258_1: R258.1 U4.M11
NETR259_1: R259.1 U4.N11
NETR260_2: R260.2 U4.N10
NETR261_1: R261.1 U4.M8
NETR262_1: R262.1 U4.B12
NETR263_2: R263.2 U4.C14
NETR264_2: R264.2 U4.D14
NETR265_2: R265.2 U4.E14
NETR266_2: R266.2 U4.E12
NETR267_1: R267.1 U4.H14
NETR268_1: R268.1 U4.L12
NETR269_1: R269.1 U4.M13
NETR270_1: R270.1 U4.N12
NETR271_1: R271.1 U4.M10
NETR273_1: R273.1 U4.C12
NETR274_2: R274.2 U4.C13
NETR275_2: R275.2 U4.D13
NETR276_2: R276.2 U4.E13
NETR282_1: R282.1 U9.F7
NETR285_1: R285.1 U15.J2
NETR287_2: R287.2 U22.42
NETR288_2: R288.2 U22.43
NETR289_2: R289.2 U21.20
NETR290_2: R290.2 U22.46
NETR292_1: R292.1 R293.1 R294.2 T4.1
NETSB5_1: SB5.1 U23.G1
NETSB7_1: SB7.1 U23.E3
NETSB9_1: SB9.1 U23.F2
NETSB12_2: SB12.2 U6.41
NETSB15_1: SB15.1 U22.30
NETSB16_1: SB16.1 U8.3
NETSB19_1: SB19.1 U23.E4
NETSB25_2: SB25.2 U25.3 U26.3
NETSB26_1: SB26.1 U25.4 U26.4
NETSB31_2: SB31.2 U6.31
NETSB32_2: SB32.2 U8.12
NETSB34_2: SB34.2 U8.13
NETSB48_1: SB48.1 U6.40
NETSB56_2: SB56.2 U8.11
NETSB63_2: SB63.2 U6.42
NETSB67_1: SB67.1 U24.1
NETTP12_1: TP12.1 U6.25
NETU22_15: U22.15 U23.G3
OSC_IN: C84.1 U21.5 X6.2
OSC_OUT: C85.1 U21.6 X6.1
PA0: CN5.15 SB44.2 SB46.2 SB48.2 U4.N3
PA1: CN5.14 SB33.2 SB39.2 U4.N2
PA2: CN5.13 SB40.2 SB42.2 U4.P2
PA3: CN5.18 R82.2 U4.R2
PA4: CN5.21 JP3.1 SB47.2 U4.N4
PA5: CN5.24 R113.2 U4.P4
PA6: CN4.33 CN5.20 R15.2 U4.P3
PA7: CN5.22 SB43.2 SB45.2 U4.R3
PA8: CN6.52 SB75.2 SB77.2 SB80.2 U4.F15
PA9: CN6.43 R253.1 SB72.2 U4.E15
PA10: CN6.44 JP15.2 R107.2 U4.D15
PA11: CN6.41 D5.D3 JP9.1 R281.2 SB68.2 U4.C15
PA12: CN6.42 SB66.2 SB67.2 SB71.2 U4.B15
PA13: CN6.40 R80.2 U4.A15 U21.25 U21.27
PA14: CN6.36 R87.2 U4.A14 U21.15 U21.26
PA15: CN6.32 R93.2 U4.A13 U21.17
PAR_D0: CN4.23 CN6.58 JP5.3 SB82.1 U4.H15
PAR_D1: CN1.7 CN4.24 CN6.56 R277.1 U4.G15
PAR_D2: CN4.25 CN6.51 SB78.1 SB81.1 U4.G14
PAR_D3: CN4.26 CN6.46 R252.2 U4.F14
PAR_D4: CN4.27 CN6.53 R272.2 U4.B13
PAR_D5: CN4.28 CN6.23 U4.C11
PAR_D6: CN4.29 SB4.1
PAR_D7: CN4.30 SB17.1
PAR_D8: CN4.9 CN6.55 R17.2 R278.2 U4.B14
PAR_D9: CN4.10 CN6.28 CN17.5 U4.A12
PAR_D10: CN4.5 CN6.47 JP6.2 U4.B11
PAR_D11: CN4.6 CN6.57 SB83.2 U4.D12
PB0: CN5.52 SB76.2 SB79.2 U4.R5
PB1: CN5.26 SB50.2 SB51.2 U4.R4
PB2: CN5.29 R6.2 U4.M5
PB3: CN6.45 JP5.2 U4.A10
PB4: CN6.24 R103.2 U4.A9 U21.19
PB5: CN5.4 SB28.2 SB29.2 U4.A8
PB6: CN6.18 R40.2 R215.2 U3.7
PB7: CN4.32 CN6.21 U4.B5
PB8: CN6.31 CN15.44 CN18.40 R5.1 R151.2 R179.1 R287.1 R295.1 T5.3 U4.A7
PB9: CN6.14 CN15.40 CN18.38 R4.1 R152.2 R172.1 R288.1 R296.1 T6.3 U4.B4
PB10: CN5.33 R94.2 U4.P12
PB11: CN5.36 R98.2 U4.R13
PB12: CN5.41 R254.2 SB70.2 SB74.2 U4.L13
PB13: CN5.43 R109.2 R255.2 U4.K14
PB14: CN5.35 SB64.2 SB65.2 U4.R14
PB15: CN5.38 SB61.2 SB62.2 U4.R15
PC0: CN5.11 JP3.3 SB34.1 U4.M2
PC1: CN5.16 SB31.1 SB41.1 U4.M3
PC2: CN5.23 R233.1 SB49.1 U4.M4
PC3: CN5.27 SB54.1 SB59.1 U4.L4
PC4: CN5.25 SB52.1 SB53.1 U4.N5
PC5: CN5.46 SB69.1 SB73.1 U4.P5
PC13: CN6.6 R203.2 U4.D1
PC14: R19.2 SB35.1 U4.E1
PC15: R18.2 SB36.1 U4.F1
PD4: CN11.28 U4.D11 U9.G2 U16.A2
PD5: CN11.26 R99.2 U4.C10
PD7: CN11.24 R85.2 U4.A11
PE0: CN11.25 U4.A6 U15.K9 U16.A1
PE1: CN11.23 U4.A5 U15.K1 U16.B2
PF6: CN5.7 R25.2 R227.2
PF7: CN5.8 R23.2 R217.1
PF8: CN5.17 R228.1 R237.2
PF9: CN5.12 R27.2 R216.2
PF10: CN5.9 R222.2 U3.16
PF11: CN10.8 R48.2 U15.J9
PG7: CN5.47 U4.J14 U23.D3
PG8: CN10.40 R267.2 U15.J1
PG9: CN11.27 R135.2 U4.D9
PG11: CN6.33 R242.1 SB60.1 U4.B8
PG13: CN6.25 R36.1 SB8.1 U4.B3
PG14: CN6.29 R235.1 U4.A4
PG15: CN11.19 R41.2 U15.K7
PH0: R20.1 SB37.1 U4.G1
PH1: C23.1 SB38.1 U4.H1 X1.1
PH2: CN11.2 R285.2 U4.K4
PH3: CN10.1 R243.1 U15.J8
PH4: CN5.28 SB56.1 SB57.1 U4.H4
PH5: CN10.2 R246.1 U15.K8
PH6: CN5.37 SB55.1 SB58.1 U4.P13
PH7: CN5.40 R42.2 U4.N13
PI4: CN11.17 U4.C3 U15.F8
PI5: CN11.15 U4.D3 U15.F2
PI8: CN6.9 R290.1 U4.C2
PI11: CN5.2 SB30.1 SB32.1 U4.F3
PI12: CN6.7 CN18.26 U4.E3
PI13: CN6.2 CN18.28 U4.G3
PI14: CN5.32 CN18.32 R214.1
PK7: CN6.8 CN15.57 R125.1 R153.2 U4.C4
PWR_ENN: R147.2 U18.3 U21.28
RESET#: B1.2 B1.3 C102.2 CN18.36 D2.1 D16.2 R96.2 R114.2 R213.1 U4.J1 U6.29 U21.18
STL_USB_DM: R177.2 U21.32
STL_USB_DP: R180.2 U21.33
STLINK_RX: CN24.1 JP19.3 U21.13
STLINK_TX: CN24.2 JP15.3 U21.12
STM_JTCK_SWCLK: CN20.3 U21.37
STM_JTMS_SWDIO: CN20.1 U21.34
STM_RST: C181.2 R291.1 SB84.2 U21.7
SWIM_PU_CTRL: U21.4
T_JTDO: JP5.1 R92.2 U21.16 U21.31
TOUCH_INT: CN15.4 CN18.39 U22.27
U5V_ST_LINK: C59.2 JP14.11 SB24.2 U18.6 U18.7
ULPI_D1: SB79.1 U8.23
ULPI_D2: SB50.1 U8.22
ULPI_D5: SB74.1 U8.19
ULPI_D7: SB29.1 U8.17
USB_RENUMN: R293.2 U21.38
VREF+: C108.1 C113.2 R33.2 TP6.1 U4.P1
VUSB_ST_LINK: C65.1 CN22.1 D11.1 R144.1 R147.1 R187.1 R292.2 SB24.1 U18.1 U18.2

Pads without a net: CN2 2 6 8; CN5 44 45 53 55 57; CN6 34 35 37 38; CN7 1 4 7 9; CN9 7; CN12 7; CN15 2 6 8 10 12 14 16 18 20 22 24 25 26 28 30 31 32 33 34 35 37 38 39 41 42 43 45 46 47 48 50 51 52 54 55 56 58 59 60; CN17 11 12 13 14; CN18 24 41 42 44 46 48; CN20 5; CN21 5; CN23 1 4 8; CN25 6; CN26 5 7; CN27 5 7; CN28 6; D5 A2 B1 B2 C2; D6 A2 B1 B2 C2; U1 2; U3 3 4 5 6 11 12 13 14; U5 4 8 9 11 12 14 15 18 19 21; U6 8 9 10 11 12; U9 A1 A8 B1 C1 D1 E1 F8 G1 G8 H1 H8; U13 3; U15 E3 E7 H3 H7 K2 K3; U16 E3; U21 11 14 22 40 41 42 43 45 46; U22 3 4 5 6 10 11 12 13 25 38 41; U23 A6 A8 B1 B4 B5 B7 B8 B9 C3 C4 C5 C7 C8 E1 E5 F4 F5 F6 F8 F9 G4 H2 H3 H4 H5; U24 5

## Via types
v1: diameter 0.508, hole 0.254, TOP to BOTTOM, 686 vias
v2: diameter 0.305, hole 0.152, TOP to BOTTOM, 24 vias
v3: diameter 0.61, hole 0.305, TOP to BOTTOM, 607 vias
v4: diameter 0.483, hole 0.254, TOP to BOTTOM, 41 vias
v5: diameter 0.406, hole 0.203, TOP to BOTTOM, 293 vias

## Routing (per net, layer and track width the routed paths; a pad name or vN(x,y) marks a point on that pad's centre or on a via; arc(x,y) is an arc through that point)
+1V8: length 49.6
  TOP w0.229: U23.G9 119.36,31.26 ; U23.D1 117.86,26.81 ; U23.D8 v2(118.11,30.83)
  TOP w0.254: 119.36,31.26 119.36,32.24 120.27,33.15 120.27,33.78 C73.1 ; v3(118.24,25.98) 117.86,26.36 117.86,26.81
  TOP w0.508: 115.57,41.07 C67.1 ; C67.1 116.54,41.91 ; C67.1 115.57,42.75 ; C67.1 114.6,41.91 ; U20.2 109.86,47.56 ; U20.2 109.86,45.35 ; U20.2 109.14,46.46 ; U20.2 110.57,46.46 ; X3.4 139.04,149.17 137.45,147.57 R26.2 136.37,147.57 TP1.1 ; U20.4 111.71,40.16 ; U20.4 109.86,39.05 ; U20.4 108,40.16 ; U20.4 109.86,41.26 ; v3(147.57,156.72) 147.7,156.84 148.57,156.84 148.72,156.69 CN4.1 ; C73.1 v3(120.9,33.4) ; v3(152.91,158.75) 153.16,158.5 153.16,156.97 152.88,156.69 CN4.2 ; C71.1 118.11,33.66 v3(117.86,33.4) ; C90.1 v3(118.24,25.98)
  BOTTOM w0.508: 148.46,156.87 C106.2 ; C106.2 147.81,157.48 ; C106.2 148.46,158.09 ; v3(147.07,149.22) R220.2 ; R225.2 v3(146.94,146.18) ; 152.53,158.09 C105.1 152.53,156.87 ; 144.98,150.37 135.61,150.37 TP1.1
  vias: v3(116.19,39.33) v3(116.19,38.44) v3(117.2,39.33) v3(117.2,38.44) v3(118.22,39.33) v3(118.22,38.44) v3(136.78,100.33) v3(137.67,100.33)
+2V8: length 31.8
  TOP w0.508: v3(150.93,137.95) 150.93,137.95 151.18,137.69 CN4.40 ; U2.4 134.7,152.81 ; U2.4 130.99,152.81 ; U2.4 132.84,151.7 ; U2.4 132.84,153.91 ; 139.32,152.83 C19.1 ; C19.1 138.48,153.8 ; C19.1 139.32,154.76 ; C19.1 140.16,153.8 ; 137.69,156.08 R16.1 ; R16.1 138.3,155.49 ; R16.1 138.91,156.08 ; U2.2 133.55,159.11 ; U2.2 132.13,159.11 ; U2.2 132.84,160.21 ; U2.2 132.84,158 ; CN4.39 150.17,137.69 v3(150.55,137.31) ; 131.14,155.45 TP5.1
  BOTTOM w0.508: v3(151.13,156.34) 151.03,156.34 T6.1 153.03,155.64 153.16,155.76 T5.1 ; C122.1 150.95,137.92 v3(150.93,137.95) ; v3(154.94,148.79) 154.64,149.1 R219.2 R224.2 ; C123.1 149.94,137.92 v3(150.55,137.31)
  vias: v3(138.56,152.27) v3(138.56,151.51) v3(139.32,152.27) v3(139.32,151.51) v3(140.08,152.27) v3(140.08,151.51)
+3V3: length 240.5
  TOP w0.229: U23.B2 v2(117.11,27.33) U23.C2 ; v2(118.11,27.33) 118.11,27.34 U23.D2
  TOP w0.254: U8.31 27.2,109.11 v3(27.43,109.35) 27.7,109.08 U8.30 ; CN15.36 102.32,79.69 C52.1 ; U6.48 125.27,126.96 124.84,127.38 124.33,127.38 C29.1 ; U8.25 30.2,109.19 v3(30.48,109.47) ; U8.6 24.9,105.29 v3(24.77,105.16) ; C38.2 129.77,116.11 U6.22 ; U8.16 30.2,103.23 v3(30.73,102.69) ; C34.2 135.23,121.41 134.1,122.54 133.83,122.54 133.81,122.56 133.39,122.56 133.38,122.54 U6.32 ; 118.41,32.05 118.36,32 U23.E9
  TOP w0.279: v3(61.7,36.9) 61.54,36.9 61.04,36.41 U22.24 ; v3(54.1,30.73) 54.1,30.61 53.51,30.02 U22.1 ; v3(53.26,36.62) 53.51,36.87 U22.36 ; v3(53.09,30.61) 52.75,30.61 52.45,30.9 U22.48
  TOP w0.305: U5.22 33.6,129.87 v3(33.4,129.67) ; U5.26 v3(33.02,132.47)
  TOP w0.381: U15.F9 92.66,70.37 v5(92.67,70.36) ; U9.D8 78.91,99.19 v5(79.38,98.73) ; v5(95.07,70.36) 95.06,70.37 U15.C9 ; U15.L1 88.66,78.01 v5(88.64,78.03) ; U9.G5 v4(76.38,101.9) ; v5(97.06,72.17) U15.A7 ; U15.D9 94.26,70.37 v5(94.27,70.36) ; U16.D6 66.42,71.78 v5(66.79,71.41) ; U15.M9 v5(87.46,70.57) ; U15.B7 v5(96.26,72.17) ; U15.N9 v5(86.66,70.57) ; U16.E1 65.66,75.54 v5(65.66,76.07) ; U15.B2 v5(96.26,76.97) ; v5(77.09,107.19) 76.91,107.01 U9.F1 ; U15.R7 85.4,72.57 85.06,72.23 v5(85.06,72.17) ; U15.E1 v5(93.86,77.77) ; U15.P7 v5(85.86,72.17) ; U15.L7 v5(88.26,72.17) ; U15.P2 v5(85.86,76.97) ; U16.A6 v5(69.04,71.41)
  TOP w0.508: v3(136.27,164.59) 135.51,164.59 C3.1 135.51,165.61 v3(136.27,165.61) ; R79.1 85.85,113.03 85.5,113.39 v3(85.5,113.87) ; v3(147.83,161.29) 146.56,160.02 146.56,151 v3(147.07,150.5) ; R134.2 v3(68.96,63.37) ; LD1.1 v3(27.41,15.49) ; C89.1 116.84,24.64 v3(116.59,24.89) ; v3(91.57,130.94) 91.57,131.44 C26.1 ; R108.2 v3(13.97,102.62) ; R110.1 v3(135,101.47) ; R14.2 v3(105.66,157.61) ; R171.2 v3(125.09,24.89) ; R149.1 v3(136.53,45.21) ; v3(122.45,128.96) 123.01,128.96 C29.1 ; v3(151.89,115.44) 151.89,116.46 R72.2 ; B2.4 v3(66.74,4.38) ; v3(90.04,101.47) 89.28,102.23 R106.2 ; LD2.1 v3(25.37,15.49) ; v3(107.9,92.96) 107.59,93.27 CN11.40 ; R200.1 v3(81.41,16.51) ; v3(129.29,112.52) R76.2 R75.2 ; v3(137.41,107.77) C46.2 141.1,106.68 141.6,106.17 ; R69.2 v3(137.79,120.02) ; L6.1 54.74,25.02 v3(54.74,25.15) R165.2 ; C62.1 59.16,55.88 ; C62.1 57.94,55.88 ; C62.1 58.55,55.23 ; U3.2 v3(33.78,145.16) ; R198.1 v3(75.82,16.51) ; R112.1 v3(24.13,98.55) ; C52.1 v1(100.47,79.01) ; LD3.1 v3(23.34,15.49) ; R150.1 v3(136.53,43.69) ; U24.3 131.54,22.99 131.57,22.96 v3(131.57,22.86) ; R199.1 v3(78.61,16.51) ; R207.1 v3(64.39,9.91) ; R124.2 v3(145.8,88.27) ; U20.3 108.27,46.46 ; U20.3 106.84,46.46 ; U20.3 107.56,45.35 ; U20.3 107.56,47.56 ; R120.2 v3(8.89,88.9) ; R125.2 115.82,80.77 v3(115.95,80.64) ; B2.1 v3(58.04,4.38) ; 56.26,54.66 C61.1 ; C61.1 55.3,55.5 ; C61.1 57.23,55.5 ; R118.2 v3(153.16,95.99) ; R115.1 19.24,98.87 T1.2 v3(19.24,101.41) ; R154.1 v3(51.05,38.1) ; R73.2 v3(137.67,115.82) ; R1.1 v3(134.37,166.62) ; R121.1 v3(13.97,89.79) ; v3(62.61,38.61) 63.18,39.18 CN18.50 ; R90.1 v3(135,109.09) ; C28.1 v3(61.34,128.27) ; v3(131.27,116.36) 131.27,115.9 130.68,115.32 C38.2 ; CN6.48 v3(113.53,126.75) ; R201.1 v3(84.2,16.51) ; R159.2 v3(48.39,28.45) ; R152.1 v3(72.39,36.76) ; R21.2 v3(86.11,151.64) ; R86.2 v3(80.26,110.62) ; v3(119.51,111.38) 118.8,111.38 118.03,110.62 CN12.1 ; R68.1 v3(122.43,120.02) ; R129.2 v3(146.69,80.52) ; R204.2 v3(93.73,16.76) ; C34.2 v3(136.02,122.17) ; R181.2 v3(142.11,22.99) ; R143.2 v3(136.53,53.85) ; R131.2 v3(143.38,73.41) ; R146.1 v3(136.53,50.8) ; LD4.1 v3(21.31,15.49) ; R84.2 74.04,110.11 v3(74.57,109.58) ; R123.2 v3(144.4,88.27) ; R132.2 v3(143.38,72.01) ; R83.1 v3(135,110.74) ; R148.1 v3(136.53,46.74) ; CN5.48 v3(44.7,126.75) ; v3(114.05,24.89) C87.1 ; R197.1 v3(73.03,16.51) ; 118.41,32.05 118.41,32.41 118.87,32.87 118.87,33.78 C72.1 119.51,34.54 119.63,34.67 v3(119.63,33.4) ; R89.2 v3(9.91,109.22) ; v3(132.84,166.75) C1.1 133.9,168.69 U1.7 ; R70.2 v3(137.79,118.62) ; R105.1 v3(135,103.12) ; R71.2 v3(137.79,117.22) ; R178.1 v3(122.43,21.46) ; R151.1 v3(67.82,36.7) ; C88.1 v3(115.44,24.89) ; R2.1 v3(141.99,168.78) ; CN2.5 v3(37.72,161.29) ; RV1.1 C94.1 ; R169.1 v3(40.13,24.64) ; R145.1 v3(136.53,52.32) ; C47.2 v3(138.43,104.9) ; R122.2 v3(13.97,87.88) ; R174.1 v3(140.59,26.67) ; CN17.4 v3(140.24,47.47)
  TOP w1.27: U19.2 U19.4
  BOTTOM w0.381: v5(86.66,70.57) 86.61,70.52 C172.1 ; v5(96.26,76.97) 96.14,77.09 C159.1 ; C165.1 86.49,72.8 v5(85.86,72.17) ; v5(79.38,98.73) C154.1 ; v5(65.66,76.07) 65.66,76.2 C161.1 ; v5(77.09,107.19) 76.45,106.55 C150.1 ; v5(88.26,72.17) 88.52,72.43 C164.1 ; C170.1 92.67,68.92 v5(92.67,70.36) ; v5(95.07,70.36) 95.07,70.03 96.14,68.96 C168.1 ; v5(97.06,72.17) 97.03,72.2 C162.1 ; v5(94.27,70.36) 94.27,69 C169.1 ; C158.1 86.49,77.6 v5(85.86,76.97) ; C166.1 68.96,71.33 v5(69.04,71.41) ; v5(88.64,78.03) 88.64,78.75 C157.1 ; C153.1 76.17,102.11 v4(76.38,101.9) ; C171.1 87.88,70.14 v5(87.46,70.57) ; v5(66.79,71.41) 66.42,71.04 C167.1 ; C160.1 93.6,78.03 v5(93.86,77.77) ; C163.1 95.63,72.8 v5(96.26,72.17)
  BOTTOM w0.508: R218.1 v3(147.07,150.5) ; v3(53.26,36.62) 53.34,36.7 C174.2 ; v3(54.1,30.73) 54.1,30.61 53.59,30.1 C182.2 ; C179.2 v3(53.09,30.61) ; C151.1 25.4,105.79 v3(24.77,105.16) ; C130.1 v3(55.88,137.41) ; v3(16,111.89) R279.2 ; R215.1 34.04,152.53 33.78,152.27 v3(33.66,152.27) ; C110.1 v3(33.78,145.16) ; R282.2 v3(75.82,95.38) ; C177.2 C176.1 61.09,36.45 61.54,36.9 v3(61.7,36.9) ; C183.1 v3(131.57,22.86) ; v3(30.73,102.69) 30.73,103.5 C152.1 ; C138.1 32.9,132.59 v3(33.02,132.47) ; R21.2 v3(86.11,151.64) ; C149.1 27.18,109.09 v3(27.43,109.35) ; C148.1 v3(30.48,109.47)
  vias: v1(58.02,54.63) v1(58.02,53.99) v1(58.02,53.36) v1(58.78,54.63) v1(58.78,53.99) v1(58.78,53.36) v3(43.05,44.96) v3(43.18,47.5) v3(43.31,54.86) v3(43.31,50.8) v3(55.24,52.96) v3(55.24,47.62) v3(55.24,44.58) v3(106.93,48.01) v3(107.95,48.01)
+3V3_ST_LINK: length 24.4
  TOP w0.279: U21.9 39.22,28.21 v1(39.37,28.07) ; v3(35.56,39.5) 35.22,39.16 U21.36 ; U21.24 41.53,37.2 v3(41.53,37.72) ; v1(34.44,28.68) 35.03,28.68 35.22,28.87 U21.1 ; U21.48 32.81,30.9 v1(32.38,30.48)
  TOP w0.508: T4.3 v3(20.85,19.47) ; JP20.1 v3(30.23,17.65) ; v3(23.11,66.29) C57.1 C55.2 25.16,68.58 U17.5 ; R190.2 v3(18.92,15.49)
  BOTTOM w0.508: C180.2 40.39,29.08 v1(39.37,28.07) ; C175.2 41.53,37.47 v3(41.53,37.72) ; C173.2 35.05,38.99 v3(35.56,39.5) ; v3(36.48,28.16) 36.32,28.32 R291.2 ; v3(40.01,35.81) 40.01,35.69 R286.1 ; C178.2 v1(32.38,30.48)
+5V: length 282
  TOP w0.508: TP14.1 12.7,65.99 ; TP14.1 12.7,64.06 ; TP14.1 11.73,65.02 ; TP14.1 13.67,65.02 ; 47.35,64.24 C58.1 ; C58.1 47.35,65.81 ; C58.1 45.79,65.02 ; JP14.6 8.08,70.23 ; JP14.6 7.11,71.2 ; JP14.6 6.15,70.23 ; JP14.6 7.11,69.27 ; JP14.8 8.08,67.69 ; JP14.8 7.11,68.66 ; JP14.8 7.11,66.73 ; JP14.8 6.15,67.69 ; 7.11,65.15 7.11,66.12 ; 7.11,65.15 7.11,64.19 ; 7.11,65.15 8.08,65.15 ; 6.15,75.31 JP14.2 ; JP14.2 8.08,75.31 ; JP14.2 7.11,74.35 ; JP14.2 7.11,76.28 ; 128.8,159.94 124.87,159.94 121.23,156.31 121.23,143.23 118.87,140.87 118.87,120.73 117.27,119.13 CN6.60 ; 129.83,159.11 U2.3 ; U2.3 130.54,160.21 ; U2.3 130.54,158 ; R130.2 v3(12.95,76.33) ; 7.11,71.81 JP14.4 ; JP14.4 7.11,73.74 ; JP14.4 8.08,72.77 ; JP14.4 6.15,72.77 ; D15.1 46.23,20.43 46.23,25.15 43.18,28.19 v3(40.77,28.19) ; JP14.12 7.11,63.58 ; JP14.12 8.08,62.61 ; JP14.12 7.11,61.65 ; U7.5 v3(20.7,114.49) 21.02,114.49 21.41,114.88 21.41,117.17 22.94,118.69 29.79,118.69 31.11,120.02 34.54,120.02 38.48,116.08 45.97,116.08 46.82,116.93 CN5.60 ; 46.61,56.93 U19.3 ; U19.3 45.72,58.85 ; U19.3 46.61,60.77 ; U19.3 47.5,58.85 ; U11.5 9.72,96.2 v3(9.02,96.9) ; v3(103.25,76.05) 103.25,68.55 95.28,60.58 65.53,60.58
  TOP w0.762: 47.75,67.31 49.04,68.6 60.12,68.6 65.53,63.19 L4.1
  L3_SIG w0.508: CN1.25 72.74,168.61 ; CN1.25 73.71,167.64 ; CN1.25 71.78,167.64 ; v3(40.77,28.19) 40.51,28.19 38.38,30.33 34.9,30.33 31.88,33.35 31.88,42.04 29.84,44.07 29.84,60.83 26.92,63.75 v3(26.92,64.26) ; 7.11,71.81 JP14.4 ; JP14.4 7.11,73.74 ; JP14.4 8.08,72.77 ; JP14.4 6.15,72.77 ; JP14.2 8.08,75.31 ; JP14.2 7.11,76.28 ; JP14.2 7.11,74.35 ; JP14.2 6.15,75.31
  BOTTOM w0.508: L8.1 105.82,78.62 v3(103.25,76.05)
  vias: v3(13.18,93.75) v3(13.18,92.91) v3(20.73,115.27) v3(129.06,161.9) v3(129.82,161.9)
D5V: length 22.1
  TOP w0.508: D7.1 16.26,85.09 v1(15.11,86.23)
  TOP w0.711: CN6.49 v1(108.08,125.48)
  TOP w0.762: 43.51,125.48 CN5.49 39.34,125.48
  L3_SIG w0.508: JP14.7 5.54,67.69 ; JP14.7 4.57,68.66 ; JP14.7 4.57,66.73 ; JP14.7 3.61,67.69
  vias: v1(14.91,96.04) v1(15.57,96.06) v1(27,121.97) v1(27.89,122.1) v1(44.3,121.34) v1(44.83,120.98) v1(107.31,125.48)
GND: length 678.2
  TOP w0.203: D3.B1 8.56,116.13 v3(8.76,116.33) 8.56,116.53 D3.B2 ; D4.B1 8.56,114.48 v3(8.76,114.68) 8.56,114.88 D4.B2
  TOP w0.229: U23.C1 117.36,26.81 v3(116.96,26.41) ; v2(118.11,27.83) 118.36,27.58 U23.E2 ; U23.E8 v2(118.61,30.33) 118.36,30.08 U23.E7 ; v3(115.62,26.44) 115.72,26.44 U23.A1 ; U23.D6 117.86,29.58 v2(118.11,29.33) ; U23.G5 119.36,29.09 119.61,29.33 v2(119.61,29.33) ; U23.A5 115.98,29.08 v3(115.7,29.36) ; v3(120.21,32.14) 120.21,31.43 U23.H9 ; U23.A3 115.7,28.08 v3(115.7,28.08) 115.7,28.32 115.96,28.58 U23.A4 ; v2(119.11,29.83) U23.F7
  TOP w0.254: U6.35 133.36,124.04 v3(133.6,124.28) 133.34,124.54 U6.36 ; CN15.7 109.32,89.3 109.37,89.36 v3(109.37,89.41) ; U6.15 126.27,116.36 126.87,115.75 v3(126.87,115.32) ; U8.2 25.29,107.29 v3(25.15,107.44) 25.5,107.8 U8.1 ; v3(106.55,85.85) 106.55,85.87 106.32,86.11 CN15.19 ; v3(128.52,118.75) 128.27,118.49 U6.19 ; D6.D2 v3(8,82.93) ; v3(127.15,124.84) 126.36,124.84 125.77,125.44 U6.47 ; CN15.1 110.82,86.39 110.27,85.84 v3(109.6,85.84) ; CN15.13 107.82,89.41 v3(107.8,89.43) ; v3(8,97.28) D5.D2
  TOP w0.279: v3(58.94,36.45) 59.48,35.9 U22.23 ; U22.8 57.01,30.21 v3(56.76,30.47) ; U21.35 35.72,38.77 36.2,39.24 36.25,39.24 v3(36.27,39.27) ; U21.8 38.72,28.31 v3(38.5,28.08) ; U22.47 v3(53.09,31.41) ; v3(41.15,35.81) 41.24,35.9 U21.23 ; U22.35 54.01,38.99 53.99,39.1 v3(53.72,39.37) ; U21.47 v3(32.38,31.41)
  TOP w0.305: v3(33.27,130.68) 33.44,130.52 U5.23 ; U25.5 122.96,14.5 v3(122.56,14.1) ; U13.2 145.29,81.41 R128.1
  TOP w0.356: v3(33.4,131.82) U5.25
  TOP w0.381: v5(93.47,70.36) 93.46,70.37 U15.E9 ; U9.E8 77.91,99.13 v5(78.26,98.78) ; U15.R3 v5(85.06,76.17) ; U4.K9 v5(77.22,136.89) 76.82,137.29 U4.K8 ; v5(79.61,135.29) U4.G10 ; v5(87.04,78.03) 87.06,78.01 U15.N1 ; U9.H7 74.45,100.37 v5(74.3,100.22) ; U4.K10 v5(76.41,135.29) ; v5(76.41,139.29) U4.K6 ; v3(5.59,101.35) 5.24,100.99 CN13.5 ; v5(74.17,105.42) 74.22,105.37 U9.H2 ; v5(79.61,138.49) U4.F7 ; U15.P3 v5(85.86,76.17) ; U4.F6 v5(80.41,139.29) ; U15.C1 v5(95.46,77.77) ; v5(77.21,135.29) 77.61,135.69 U4.J10 ; U4.K7 v5(76.41,138.49) ; U15.M1 87.86,78.01 v5(87.84,78.03) ; U15.L9 v5(88.26,70.57) ; U4.G12 v5(79.61,133.69) ; U15.B8 v5(96.26,71.37) ; U26.5 v3(2.31,8.28) ; CN14.5 v3(2.95,86.64) ; U15.D1 v5(94.66,77.77) ; v5(79.61,139.29) U4.G6 ; U4.F8 v5(80.41,136.89) ; v5(80.41,142.49) U4.F2 ; U4.M1 v5(74.81,143.29) ; v3(145.16,78.23) 145.29,78.11 U14.2 ; U10.2 v3(127.03,100.71) ; U15.L3 v5(88.26,76.17) ; v5(79.5,136.91) 79.59,136.91 U4.F9 ; U4.L6 v5(75.61,139.29) ; U4.H6 v5(78.01,138.49) ; v5(77.19,138.48) 77.2,138.48 U4.J6 ; U15.P8 v5(85.86,71.37) ; U16.D1 v5(66.41,76.07) ; U15.F1 v5(93.06,77.77) ; U15.B3 v5(96.26,76.17) ; U4.F10 v5(80.41,135.29) ; U15.A3 v5(97.06,76.17) ; U4.H10 v5(78.01,135.29) ; U16.E6 v5(65.29,71.41) ; v5(74.01,143.29) U4.N1
  TOP w0.508: R210.2 v3(115.95,10.67) ; U20.1 112.15,47.56 ; U20.1 112.15,45.35 ; U20.1 112.87,46.46 ; 51.69,56.93 U19.1 ; U19.1 51.69,60.77 ; U19.1 50.8,58.85 ; U19.1 52.58,58.85 ; v3(32.64,46.1) 32.51,46.1 31.75,46.86 C65.2 31.75,47.52 32.66,48.44 v3(32.69,48.44) ; C44.2 v3(3.56,105.41) ; C35.2 v3(3.56,120.78) ; C40.2 31.51,112.27 ; C40.2 v3(30.86,113.28) ; C40.2 30.86,111.66 ; C24.1 v3(19.68,148.46) ; C16.1 v3(104.27,157.61) ; LD12.1 v3(15,7.5) ; C61.2 57.23,58.29 ; C61.2 56.26,59.13 ; C61.2 55.3,58.29 ; C61.2 56.26,57.45 ; 34.19,25.65 R168.1 ; R168.1 35.41,25.65 ; R168.1 v3(34.8,24.77) ; v3(43.31,118.49) 42.67,119.13 CN5.59 ; C36.2 v3(5.08,120.78) ; v3(82.55,148.21) 82.85,148.51 C22.2 ; CN18.1 v3(93.66,46.6) ; 25.64,112.27 C39.2 ; C39.2 v3(26.29,113.41) ; C39.2 26.29,111.66 ; 32.92,25.65 R167.1 ; R167.1 v3(33.53,24.77) ; R167.1 34.14,25.65 ; CN12.13 v3(119,103) ; U26.2 4.02,8.88 v3(4.62,9.47) ; C6.1 v3(67.31,161.28) ; v3(32.66,58.42) 33.27,58.42 C59.1 33.15,57.53 v3(32.64,57.53) ; U7.2 v3(18.31,113.54) ; C74.2 v3(122.3,37.08) ; R170.1 42.27,25.65 ; R170.1 41.05,25.65 ; R170.1 v3(41.66,24.77) ; C104.2 v3(8,6.22) ; v3(81.53,148.21) 81.58,148.26 C21.2 ; CN10.29 v3(53.54,99.62) ; CN18.19 82.23,46.55 v3(82.55,46.86) ; U1.5 135.8,168.9 136.02,168.68 v3(136.02,168.66) ; v3(113.39,150.7) 113.56,150.88 CN6.10 ; CN4.7 v3(147.62,153.69) ; 29.84,30.76 R157.1 ; R157.1 29.84,31.98 ; R157.1 v3(28.83,31.37) ; CN11.10 103.63,112.32 v3(103.38,112.06) ; v3(140.76,4.08) CN27.3 v3(138.37,6.21) ; C45.2 v3(5.08,105.41) ; CN12.17 118.11,100.46 118.67,101.02 119.18,101.02 v3(119.25,101.09) ; R211.2 v3(117.47,10.67) ; CN15.61 v3(109.68,84.66) ; C48.2 v3(31.88,97.28) ; CN10.30 v3(54.81,99.62) ; U24.2 131.54,24.26 131.57,24.29 v3(131.57,24.38) ; C60.2 27.13,57.28 ; C60.2 24.38,59 ; C60.2 24.38,55.55 ; C37.2 v3(19.68,117.73) ; R13.2 v3(89.92,161.29) ; C82.1 v3(58.55,26.29) ; v3(96.14,137.03) 95.89,137.29 R39.1 ; v3(130.81,165.61) 131.7,165.61 C3.2 131.7,164.59 v3(130.81,164.59) ; CN10.10 v3(54.74,112.32) ; C4.2 v3(140.59,163.83) ; CN11.29 v3(101.98,99.62) ; X3.2 v3(144.15,143.23) ; v3(74.55,10.41) 75.18,9.78 B4.9 ; C49.2 v3(4.45,92.58) ; B1.4 v3(52.45,4.38) ; R97.1 v3(11.43,106.68) ; C71.2 v3(118.11,37.08) ; C68.1 v3(112.9,35.94) ; C99.1 v3(82.8,16.51) ; v3(17.78,104.9) 17.65,104.78 R101.1 ; B4.7 v3(75.69,11.18) ; CN17.6 v3(140.32,49.67) ; CN6.59 111.23,119.13 111.99,118.36 v3(112.01,118.36) ; U1.8 v3(132.95,168.76) ; C67.2 115.57,45.54 ; C67.2 114.6,44.7 ; C67.2 116.54,44.7 ; CN4.11 148.26,151.69 v3(147.96,151.38) ; v3(102.31,112.06) 102.06,112.32 CN11.9 ; C8.1 61.37,158.47 v3(61.37,157.67) ; v3(111.89,156.46) 111.38,155.96 CN6.1 ; v3(118.87,98.3) 117.98,99.19 CN12.19 ; CN15.64 v3(93.73,84.66) ; C53.1 21.72,69.98 v3(21.46,70.23) ; CN5.10 v3(44.7,150.88) ; 57.94,57.4 C62.2 ; C62.2 58.55,58.05 ; C62.2 59.16,57.4 ; R208.1 v3(105.66,8.38) ; v3(75.95,161.28) 75.96,161.28 76.71,160.53 C11.2 ; v3(39.37,131.83) CN5.39 ; CN12.5 118.75,108.08 119,108.33 v3(119,108.48) 119,108.53 118.59,108.94 118.52,108.94 118.11,109.35 CN12.3 ; U11.2 v3(10.67,94.49) ; CN18.34 v3(73.34,42.42) ; L1.1 v3(6.6,120.78) ; CN4.3 148.47,155.69 v3(148.08,156.08) ; v3(150.52,138.94) 150.27,138.94 150.02,138.69 CN4.37 ; C20.2 v3(73.91,151.64) ; C58.2 53.02,65.02 ; C58.2 51.45,64.24 ; C58.2 51.45,65.81 ; R22.2 87.88,151.22 ; R22.2 87.27,150.62 ; R22.2 88.49,150.62 ; U3.10 v3(24,151.51) ; C33.1 134.54,125.04 v3(134.54,125.17) 134.54,125.27 C30.2 ; R77.1 v3(132.08,112.52) ; B4.8 v3(82.42,4.45) ; C52.2 v3(101.63,76.45) ; CN4.21 148.46,146.69 v3(147.96,147.19) ; v3(32.94,76.15) BT1.2 v3(32.94,80.49) ; CN14.10 v3(3.02,85.34) ; R161.2 v3(129.29,28.83) ; v3(76.43,124.43) 76.43,123.77 C31.2 76.45,122.73 76.45,121.92 v3(77.09,121.28) ; B4.10 82.81,5.96 v3(83.44,5.33) ; CN5.30 v3(44.83,138.18) ; B3.1 v3(91.63,4.38) ; CN18.20 v3(82.23,38.61) ; C10.1 68.58,158.5 v3(68.58,157.76) ; C47.1 v3(134.75,104.9) ; v3(118.97,102.16) 118.54,101.73 CN12.15 ; 24.77,110.13 C42.2 ; C42.2 24.12,110.74 ; C42.2 v3(24.77,112.01) ; C38.1 v3(130.68,112.52) ; R162.2 v3(129.29,27.43) ; C13.1 v3(84.2,161.42) ; U17.2 v3(29.46,68.83) ; C83.1 v3(55.75,25.15) ; C72.2 v3(119.51,37.08) ; T2.2 v3(12.83,82.87) ; v3(75.69,148.21) 75.44,148.46 C23.2 ; C87.2 v3(114.05,21.34) ; C91.2 v3(121.03,21.34) ; C73.2 v3(120.9,37.08) ; CN6.30 v3(113.53,138.18) ; L3.1 v3(62.61,53.65) ; v3(95.15,150.22) 94.97,150.22 R24.1 ; v3(155.07,151.76) 154.38,151.76 154.31,151.69 CN4.12 ; C43.2 v3(32.38,111.89) ; CN6.19 v3(112.14,144.53) ; v3(83.44,124.17) 84.5,124.17 C32.2 ; C95.1 v3(71.5,16.51) ; 142.11,152.83 C19.2 ; C19.2 142.11,154.76 ; C19.2 142.95,153.8 ; C19.2 141.27,153.8 ; CN10.9 v3(53.29,112.32) ; CN15.62 v3(103.38,84.66) ; CN18.37 v3(70.8,46.42) ; v3(48.01,30.99) R158.2 R156.2 ; CN12.11 v3(119,104.27) ; C94.2 v3(36.07,15.49) ; C78.1 v3(110.62,30.61) ; C18.1 C7.1 v3(73.66,161.26) ; CN11.30 v3(103.38,99.62) ; C34.1 v3(137.79,121.41) ; C97.1 v3(77.22,16.51) ; C84.2 v3(36.32,24.77) ; C98.1 v3(80.01,16.51) ; R212.1 v3(143.13,4.45) ; CN6.39 v3(112.01,131.83) ; C9.1 v3(62.48,157.73) ; v3(84.56,114.48) 84.33,114.25 C41.2 ; R7.2 v3(138.3,161.8) ; CN13.10 v3(3.02,99.69) ; C89.2 v3(116.84,21.34) ; R195.2 v3(38.48,12.83) ; C76.1 v3(110.62,32) ; CN4.4 v3(155.31,155.69) ; CN18.30 v3(75.88,42.34) ; C56.1 v3(33.27,67.82) ; C17.2 v3(67.31,157.43) ; R74.1 v3(13.72,114.81) ; C102.1 v3(52.2,12.19) ; C90.2 v3(118.24,21.34) ; C96.1 v3(74.42,16.51) ; R136.1 v3(143.51,65.53) ; R176.1 140.61,24.23 v3(140.61,23.24) ; CN18.2 v3(93.66,37.47) ; C27.1 v3(25.02,129.29) ; LD10.2 v3(13.97,79.25) ; v3(122.45,130.07) 123.42,130.07 C29.2 ; CN6.50 v3(113.53,125.48) ; B3.4 v3(97.35,4.38) ; C54.1 v3(33.27,69.72) ; v3(131.57,163.32) 131.57,162.56 C5.2 132.72,162.43 v3(132.72,163.32) ; C2.2 v3(138.94,166.37) ; C57.2 v3(21.46,67.18) ; CN17.9 v3(140.52,53.02) ; R202.1 v3(89.15,12.95) ; v3(143.38,80.52) R128.1 ; R164.1 51.44,25.65 v3(52.07,25.02) ; C79.2 v3(126.06,30.23) ; C88.2 v3(115.44,21.35) ; C85.2 v3(38.61,24.77) ; v3(153.7,147.45) 153.7,147.35 153.04,146.69 CN4.22 ; R116.1 v3(10.67,98.81) ; C12.1 80.98,160.27 v3(80.24,159.54) ; CN2.7 v3(37.85,158.75) ; v3(150.9,139.62) 150.9,139.57 151.78,138.69 CN4.38 ; C86.2 v3(61.98,24.26) ; R184.2 v3(117.73,16.26) ; R173.2 v3(138.94,26.67) ; v3(43.31,156.72) 42.55,155.96 CN5.1 ; C55.1 v3(21.46,68.58) ; U18.4 v3(37.49,52.2) ; B1.1 v3(43.5,4.38) ; C93.2 v3(128.4,15.62) ; CN4.16 155.01,149.69 v3(155.02,149.68) ; C15.2 v3(91.31,161.29) ; D14.3 v3(138.56,17.65) ; v3(155.45,153.69) CN4.8 ; R91.1 v3(22.61,109.47) ; R206.2 v3(61.47,9.91) ; R133.1 v3(143.38,70.48) ; B4.5 v3(82.3,11.18) ; R137.1 v3(143.64,62.48) ; R141.1 v3(38.35,58.8) ; CN12.9 v3(119,105.54) ; C14.1 v3(87,161.42) ; CN5.50 v3(44.83,125.48) ; C70.2 v3(116.71,37.08) ; CN5.19 v3(43.69,144.53) ; R127.1 v3(13.97,81.28) ; CN15.63 v3(97.54,84.66) ; C46.1 v3(134.87,106.68) ; v3(19.68,107.95) 19.05,108.58 R88.1 ; C1.2 v3(131.32,168.66) ; C77.2 v3(126.03,31.5)
  L3_SIG w0.508: 36.09,93.52 TP13.1 ; TP13.1 35.13,94.49 ; TP13.1 36.09,95.46 ; TP13.1 37.06,94.49 ; 101.27,4.06 TP16.1 ; TP16.1 103.2,4.06 ; TP16.1 102.23,5.03 ; TP16.1 102.23,3.1 ; 152.78,66.98 CN16.16 ; CN16.16 153.75,67.94 ; CN16.16 151.82,67.94 ; CN16.16 152.78,68.91 ; 141.6,111.25 142.52,111.25 ; 141.6,111.25 140.69,111.25 ; 141.6,111.25 141.6,110.34 ; 141.6,111.25 141.6,112.17 ; CN23.11 147.19,8.76 ; CN23.11 148.54,6.27 ; CN23.11 147.19,3.78 ; CN23.11 145.85,6.27 ; CN25.2 125.63,11.92 ; CN25.2 123.8,11.92 ; CN25.2 124.71,12.84 ; CN25.2 124.71,11.01 ; CN16.6 153.75,80.64 ; CN16.6 152.78,79.68 ; CN16.6 152.78,81.61 ; CN16.6 151.82,80.64 ; CN28.2 7.26,11.7 ; CN28.2 6.35,10.78 ; CN28.2 6.35,12.61 ; CN28.2 5.44,11.7 ; 2.44,89.49 CN14.8 1.28,90.4 ; CN23.3 147.02,18.8 ; CN23.3 145.8,19.89 ; CN23.3 145.8,17.7 ; CN23.3 144.58,18.8 ; 148.59,13.54 CN23.6 ; CN23.6 149.81,14.63 ; CN23.6 148.59,15.72 ; CN23.6 147.37,14.63 ; 2.44,103.85 CN13.8 1.28,104.75 ; CN16.8 152.78,79.07 ; CN16.8 151.82,78.11 ; CN16.8 152.78,77.14 ; CN16.8 153.75,78.11 ; RV1.3 32.79,8.13 ; RV1.3 32,8.92 ; RV1.3 31.22,8.13 ; RV1.3 32,7.34 ; 146.05,114.68 CN9.13 ; CN9.13 148.84,114.68 ; CN9.13 147.44,113.28 ; 1.6,51.51 L5.5 ; L5.5 1.6,53.9 ; L5.5 2.8,52.7 ; 152.78,82.22 CN16.4 ; CN16.4 153.75,83.19 ; CN16.4 151.82,83.19 ; CN16.4 152.78,84.15 ; CN13.6 4.46,98.16 ; CN13.6 5.46,97.42 ; CN13.6 3.46,97.42 ; CN13.6 4.46,96.68 ; L5.6 9.1,56.4 ; L5.6 9.1,54.01 ; L5.6 10.3,55.21 ; L5.6 7.91,55.21 ; CN22.4 10.29,23.06 ; CN22.4 9.45,22.23 ; CN22.4 10.29,21.39 ; CN22.4 11.13,22.23 ; CN16.10 153.75,75.56 ; CN16.10 151.82,75.56 ; CN16.10 152.78,74.6 ; CN16.10 152.78,76.53 ; 1.28,80.29 CN14.9 2.44,81.19 ; CN16.12 152.78,73.99 ; CN16.12 151.82,73.03 ; CN16.12 153.75,73.03 ; CN16.12 152.78,72.06 ; 53.14,17.91 JP21.1 ; JP21.1 55.07,17.91 ; JP21.1 54.1,16.94 ; JP21.1 54.1,18.87 ; 146.05,98.93 CN9.14 ; CN9.14 147.44,100.33 ; CN9.14 148.84,98.93 ; CN9.14 147.44,97.53 ; CN28.5 6.35,5.72 ; CN28.5 5.44,4.81 ; CN28.5 6.35,3.89 ; CN28.5 7.26,4.81 ; 2.44,95.54 CN13.9 1.28,94.64 ; 5.83,29.62 CN22.5 ; CN22.5 7.62,27.83 ; CN22.5 9.41,29.62 ; CN22.5 7.62,31.41 ; CN14.6 4.46,83.81 ; CN14.6 4.46,82.33 ; CN14.6 3.46,83.07 ; 4.46,101.23 CN13.7 ; CN13.7 4.46,102.71 ; CN13.7 5.46,101.97 ; CN13.7 3.46,101.97 ; CN21.2 47.88,40.08 ; CN21.2 47.88,38.15 ; CN21.2 48.84,39.12 ; CN21.2 46.91,39.12 ; CN16.18 153.75,65.41 ; CN16.18 152.78,66.37 ; CN16.18 151.82,65.41 ; CN16.18 152.78,64.44 ; 151.82,62.87 CN16.20 ; CN16.20 152.78,61.9 ; CN16.20 152.78,63.83 ; CN16.20 153.75,62.87 ; 7.62,15.63 CN22.6 ; CN22.6 7.62,19.22 ; CN22.6 5.83,17.42 ; CN22.6 9.41,17.42 ; 152.78,69.52 CN16.14 ; CN16.14 151.82,70.48 ; CN16.14 152.78,71.45 ; CN16.14 153.75,70.48 ; 147.19,28.83 CN23.10 ; CN23.10 145.85,31.32 ; CN23.10 147.19,33.81 ; CN23.10 148.54,31.32 ; 4.46,86.88 CN14.7 ; CN14.7 4.46,88.36 ; CN14.7 3.46,87.62 ; L5.4 7.8,52.7 ; L5.4 5.41,52.7 ; L5.4 6.6,51.51 ; L5.4 6.6,53.9
  BOTTOM w0.102: 85.09,141.48 C119.2
  BOTTOM w0.381: v5(82.81,138.49) 82.93,138.37 C125.2 84.2,137.79 ; v5(77.98,141.68) 78.05,141.6 78.74,141.6 ; C128.2 74.3,137.17 v5(74.01,136.89) ; v5(71.43,134.75) 71.43,135.43 C135.2 ; C132.2 77.47,135.55 v5(77.21,135.29) ; v5(70.64,141.38) 70.74,141.48 C116.1 ; v5(74.17,105.42) 74.22,105.42 74.68,105.88 C150.2 ; C165.2 86.49,75.54 v5(85.86,76.17) ; v5(78.74,137.16) 78.66,137.08 C134.2 ; v5(79.61,139.29) 78.75,138.43 C121.2 ; v5(88.26,76.17) 88.52,75.91 C164.2 ; v5(96.26,76.17) 95.63,75.54 C163.2 ; v5(85.14,134.9) 85.14,135.06 84.2,136 84.2,136.14 ; v5(74.81,143.29) 74.68,143.42 C113.1 ; C127.2 77.47,138.2 v5(77.19,138.48) ; C131.2 79.76,136.65 v5(79.5,136.91) ; v5(79.61,138.49) 79.76,138.34 C126.2 ; C120.2 71.37,138.73 v5(71.37,138.33) 71.37,138.3 71.62,138.05 C129.2 ; C166.2 68.1,68.71 v3(67.82,68.99) ; C162.2 97.03,76.14 v5(97.06,76.17) ; v5(79.61,133.69) 79.4,133.48 78.92,133.48 78.66,133.22 ; C153.2 75.2,100.22 v5(74.3,100.22)
  BOTTOM w0.508: C144.2 128.91,123.95 v3(128.91,124.97) 128.78,125.09 C142.1 ; C148.2 28.96,107.95 v3(28.45,107.44) ; v5(85.72,142.09) 85.36,141.73 85.34,141.73 85.09,141.48 ; C175.1 40.77,36.2 v3(41.15,35.81) ; v3(95.12,80.64) 95.76,80.64 C159.2 ; C111.2 83.31,144.15 v3(83.57,144.4) ; C177.1 C176.2 v3(58.94,36.45) ; C157.2 87.5,80.64 v3(87.38,80.77) 87.25,80.64 C158.2 ; v3(32.38,31.41) 32.98,32 C178.1 ; v3(150.52,138.94) 150.37,139.09 149.71,139.09 C123.2 ; v3(67.21,69.49) C167.2 ; v3(58.67,147.57) 58.67,146.69 C109.2 57.78,146.81 v3(57.78,147.57) ; C174.1 53.34,38.99 v3(53.72,39.37) ; C137.1 33.78,130.68 v3(33.27,130.68) 32.51,130.68 C138.2 ; L9.1 104.3,80.57 v3(103.81,80.09) ; v3(63.25,142.44) 63.25,143.13 C114.2 64.26,143.13 v3(64.26,142.44) ; v3(29.84,106.05) 30.73,105.16 C152.2 ; C168.2 v3(96.14,66.29) ; C154.2 v3(79.38,95.25) ; v3(58.67,142.37) 58.67,143.26 C115.2 57.78,143.13 v3(57.78,142.37) ; C105.2 v3(155.07,157.48) ; T8.2 13.65,105.09 v3(13.84,105.28) ; C122.2 151.71,139.62 v3(150.9,139.62) ; v3(77.34,122.05) 77.34,122.48 C143.2 ; v1(78.97,126.99) 78.98,127 78.98,129.52 79.12,129.67 C141.2 C140.2 ; v3(11.56,108.97) 11.56,109.5 T7.2 ; 34.8,146.18 v3(33.78,146.18) ; v3(25.15,107.44) 25.65,107.95 C149.2 ; R234.1 89.15,140.72 v3(88.52,141.35) ; C161.2 v3(65.41,78.36) ; C118.2 v3(58.93,139.95) ; C169.2 v3(95,67.31) ; R231.1 v3(88.65,143.51) ; SB84.1 C181.1 39.12,29.08 38.5,28.46 v3(38.5,28.08) ; C170.2 v3(92.58,66.29) ; v3(94.61,79.88) 94.23,80.26 C160.2 ; v3(27.05,104.65) 26.67,104.27 C151.2 ; R289.1 40.77,32.51 40.39,32.13 v3(40.39,31.75) 40.26,31.62 40.26,30.86 C180.1 ; v3(53.09,31.41) 52.54,31.41 52.32,31.62 51.82,31.62 ; C182.1 v3(54.61,28.19) ; R294.1 19.3,19.56 v3(19.05,19.3) ; R229.1 95.5,145.03 v3(96.01,144.53) ; C106.1 v3(151.26,157.48) ; C112.2 79.12,144.65 79.5,145.03 v3(79.48,145.03) ; C145.2 v3(130.3,120.27) ; C172.2 C171.2 88.7,67.31 v3(88.95,67.56) ; v3(36.27,39.27) 36.32,39.22 36.32,39.12 36.58,38.86 C173.1 ; C146.1 v3(127.38,120.14) ; C183.2 v3(131.57,24.38) ; C147.2 v3(23.11,112.39) ; v3(64.14,145.03) 64.14,145.92 C108.2 63.25,145.8 v3(63.25,145.03) ; R239.1 64.77,137.16 v3(64.52,137.41)
  vias: v1(23.62,59.94) v1(23.62,59.31) v1(24.38,59.94) v1(24.38,59.31) v1(25.15,59.94) v1(25.15,59.31) v1(58,60.05) v1(58,59.29) v1(58,58.53) v1(58.76,60.05) v1(58.76,59.29) v1(58.76,58.53) v1(81.92,35.43) v1(124.79,16.48) v1(124.76,14.02) v3(1.27,47.75) v3(1.4,32.64) v3(1.4,21.34) v3(2.16,1.52) v3(4.67,6.93) v3(6.45,8.08) v3(24.13,103.63) v3(27.05,107.44) v3(27.05,106.05) v3(28.45,106.05) v3(28.45,104.65) v3(28.7,1.52) v3(28.83,43.05) v3(29.84,107.44) v3(29.84,104.65) v3(30.3,82.14) v3(30.73,92.71) v3(32.54,20.37) v3(34.67,96.9) v3(38.73,101.19) v3(38.73,20.4) v3(44.58,16.76) v3(52.07,1.52) v3(59.18,1.52) v3(70.23,154.31) v3(71.63,62.1) v3(73.28,1.14) v3(74.68,155.83) v3(74.68,154.31) v3(77.34,151.89) v3(77.6,52.45) v3(83.95,54.23) v3(84.07,156.08) v3(85.98,123.44) v3(87,61.34) v3(87.88,152.53) v3(89.15,122.81) v3(90.93,156.72) v3(92.96,87.76) v3(93.09,64.64) v3(93.98,1.14) v3(94.06,26.75) v3(96.39,22.48) v3(98.04,41.4) v3(99.44,55.58) v3(101.47,28.19) v3(104.9,1.14) v3(110.62,34.29) v3(111.76,67.82) v3(112.52,62.23) v3(117.73,46.48) v3(117.73,45.59) v3(117.73,44.7) v3(118.49,46.48) v3(118.49,45.59) v3(118.49,44.7) v3(125.09,42.55) v3(125.35,60.83) v3(125.48,81.28) v3(125.57,70.1) v3(125.57,64.11) v3(126.47,15.21) v3(131.06,30.61) v3(136.65,69.34) v3(140.21,85.98) v3(140.46,99.95) v3(141.6,152.15) v3(141.6,151.38) v3(142.24,120.78) v3(142.37,130.68) v3(142.49,152.15) v3(142.49,151.41) v3(142.88,126.42) v3(143.26,89.92) v3(143.38,152.15) v3(143.38,151.41) v3(155.07,51.82) v3(155.45,74.3) v3(155.57,107.44) v3(155.57,92.46) v3(155.7,119) v3(155.7,33.02) v3(155.7,18.16) v3(155.7,6.22)
